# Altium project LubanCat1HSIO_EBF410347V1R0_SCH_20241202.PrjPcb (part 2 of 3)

## Sheet 07 USB3.SchDoc
size 420 x 297 mm
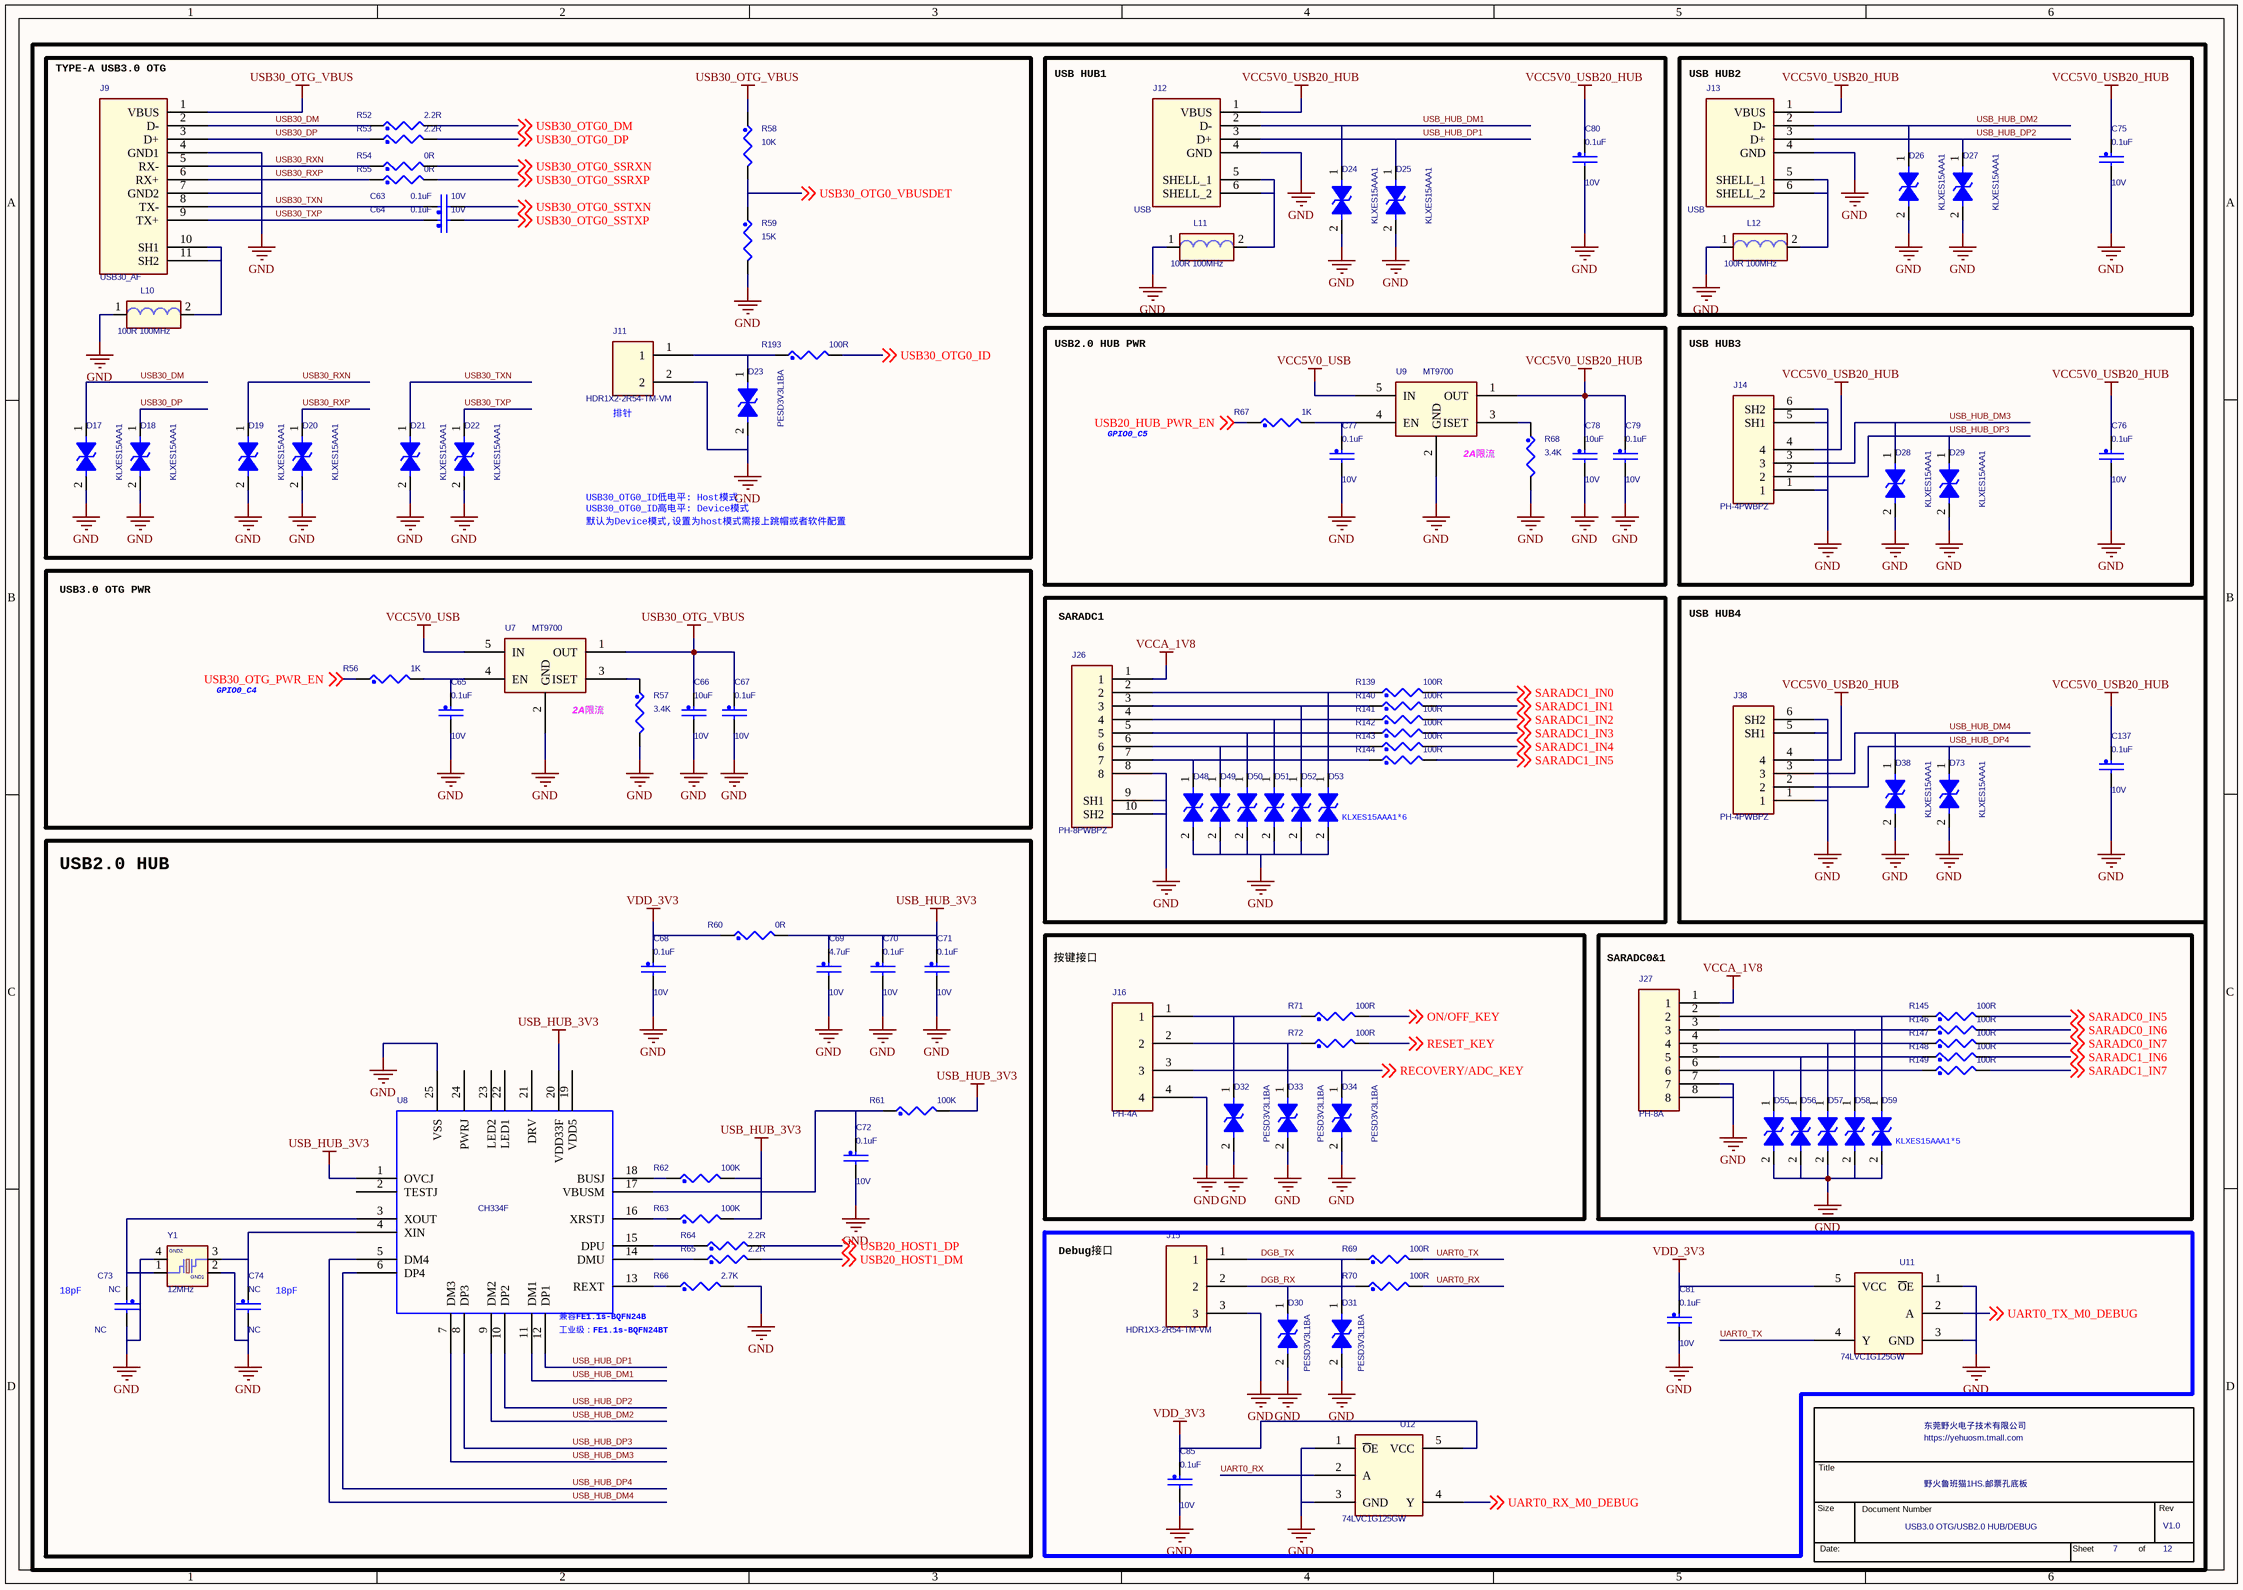
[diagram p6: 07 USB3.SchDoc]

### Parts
(Parts that share a designator on the sheet are numbered #1, #2 ... from top to bottom, then left to right.)
*#7  Page Count: 12  Page Number: 7  OrgName: 东莞野火电子技术有限公司  Title: 野火鲁班猫1HS.邮票孔底板  RevCode: V1.0  Doc: USB3.0 OTG/USB2.0 HUB/DEBUG  (hidden comment: TitleBlock_YHSCH)  (graphical)
C63  0.1uF  Voltage: 10V  [C0402]
C64  0.1uF  Voltage: 10V  [C0402]
C65  0.1uF  Voltage: 10V  [C0402]
C66  10uF  Voltage: 10V  [C0402]
C67  0.1uF  Voltage: 10V  [C0402]
C68  0.1uF  Voltage: 10V  [C0402]
C69  4.7uF  Voltage: 10V  [C0402]
C70  0.1uF  Voltage: 10V  [C0402]
C71  0.1uF  Voltage: 10V  [C0402]
C72  0.1uF  Voltage: 10V  [C0402]
C73  NC  [C0402]
C74  NC  [C0402]
C75  0.1uF  Voltage: 10V  [C0402]
C76  0.1uF  Voltage: 10V  [C0402]
C77  0.1uF  Voltage: 10V  [C0402]
C78  10uF  Voltage: 10V  [C0402]
C79  0.1uF  Voltage: 10V  [C0402]
C80  0.1uF  Voltage: 10V  [C0402]
C81  0.1uF  Voltage: 10V  [C0402]
C85  0.1uF  Voltage: 10V  [C0402]
C137  0.1uF  Voltage: 10V  [C0402]
D17  KLXES15AAA1  [D0603/SMD]
D18  KLXES15AAA1  [D0603/SMD]
D19  KLXES15AAA1  [D0603/SMD]
D20  KLXES15AAA1  [D0603/SMD]
D21  KLXES15AAA1  [D0603/SMD]
D22  KLXES15AAA1  [D0603/SMD]
D23  PESD3V3L1BA  [D0603/SMD]
D24  KLXES15AAA1  [D0603/SMD]
D25  KLXES15AAA1  [D0603/SMD]
D26  KLXES15AAA1  [D0603/SMD]
D27  KLXES15AAA1  [D0603/SMD]
D28  KLXES15AAA1  [D0603/SMD]
D29  KLXES15AAA1  [D0603/SMD]
D30  PESD3V3L1BA  [D0603/SMD]
D31  PESD3V3L1BA  [D0603/SMD]
D32  PESD3V3L1BA  [D0603/SMD]
D33  PESD3V3L1BA  [D0603/SMD]
D34  PESD3V3L1BA  [D0603/SMD]
D38  KLXES15AAA1  [D0603/SMD]
D48  KLXES15AAA1  [D0603/SMD]  (value not drawn)
D49  KLXES15AAA1  [D0603/SMD]  (value not drawn)
D50  KLXES15AAA1  [D0603/SMD]  (value not drawn)
D51  KLXES15AAA1  [D0603/SMD]  (value not drawn)
D52  KLXES15AAA1  [D0603/SMD]  (value not drawn)
D53  KLXES15AAA1  [D0603/SMD]  (value not drawn)
D55  KLXES15AAA1  [D0603/SMD]  (value not drawn)
D56  KLXES15AAA1  [D0603/SMD]  (value not drawn)
D57  KLXES15AAA1  [D0603/SMD]  (value not drawn)
D58  KLXES15AAA1  [D0603/SMD]  (value not drawn)
D59  KLXES15AAA1  [D0603/SMD]  (value not drawn)
D73  KLXES15AAA1  [D0603/SMD]
J9  USB30_AF  [USB9-A-16R5X14R45-TM]
J11  HDR1X2-2R54-TM-VM  [HDR1X2-2R54-TM-VM]
J12  USB  [USB-A-SM]
J13  USB  [USB-A-SM]
J14  PH-4PWBPZ  [ph2r0-a-1x4]
J15  HDR1X3-2R54-TM-VM  [HDR1X3-2R54-TM-VM]
J16  PH-4A  [PH-1X4-2P0]
J26  PH-8PWBPZ  [PH2R0-A-1X8]
J27  PH-8A  [ph-1x8-2p0]
J38  PH-4PWBPZ  [ph2r0-a-1x4]
L10  100R 100MHz  [L0603]
L11  100R 100MHz  [L0603]
L12  100R 100MHz  [L0603]
R52  2.2R  [R0402]
R53  2.2R  [R0402]
R54  0R  [R0402]
R55  0R  [R0402]
R56  1K  [R0402]
R57  3.4K  [R0402]
R58  10K  [R0402]
R59  15K  [R0402]
R60  0R  [R0402]
R61  100K  [R0402]
R62  100K  [R0402]
R63  100K  [R0402]
R64  2.2R  [R0402]
R65  2.2R  [R0402]
R66  2.7K  [R0402]
R67  1K  [R0402]
R68  3.4K  [R0402]
R69  100R  [R0402]
R70  100R  [R0402]
R71  100R  [R0402]
R72  100R  [R0402]
R139  100R  [R0402]
R140  100R  [R0402]
R141  100R  [R0402]
R142  100R  [R0402]
R143  100R  [R0402]
R144  100R  [R0402]
R145  100R  [R0402]
R146  100R  [R0402]
R147  100R  [R0402]
R148  100R  [R0402]
R149  100R  [R0402]
R193  100R  [R0402]
U7  MT9700  [SOT23-5]
U8  CH334F  [QFN24]
U9  MT9700  [SOT23-5]
U11  74LVC1G125GW  [SOT-353]
U12  74LVC1G125GW  [SOT-353]
Y1  12MHz  [3225]

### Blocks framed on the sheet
TYPE-A USB3.0 OTG: C63 C64 D17-D23 J9 J11 L10 R52-R55 R58 R59 R193
USB HUB1: C80 D24 D25 J12 L11
USB HUB2: C75 D26 D27 J13 L12
USB2.0 HUB PWR: C77-C79 R67 R68 U9
USB HUB3: C76 D28 D29 J14
USB3.0 OTG PWR: C65-C67 R56 R57 U7
SARADC1: D48-D53 J26 R139-R144
USB HUB4: C137 D38 D73 J38
USB2.0 HUB: C68-C74 R60-R66 U8 Y1
按键接口: D32-D34 J16 R71 R72
SARADC0&1: D55-D59 J27 R145-R149
Debug接口: C81 C85 D30 D31 J15 R69 R70 U11 U12

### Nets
GND: C65.2 C66.2 C67.2 C68.2 C69.2 C70.2 C71.2 C72.2 C73.2 C74.2 C75.2 C76.2 C77.2 C78.2 C79.2 C80.2 C81.2 C85.2 C137.2 D17.2 D18.2 D19.2 D20.2 D21.2 D22.2 D23.2 D24.2 D25.2 D26.2 D27.2 D28.2 D29.2 D30.2 D31.2 D32.2 D33.2 D34.2 D38.2 D48.2 D49.2 D50.2 D51.2 D52.2 D53.2 D55.2 D56.2 D57.2 D58.2 D59.2 D73.2 J9.4(GND1) J9.7(GND2) J11.2 J12.4(GND) J13.4(GND) J14.1 J14.5(SH1) J14.6(SH2) J15.3 J16.4 J26.8 J26.9(SH1) J26.10(SH2) J27.7 J27.8 J38.1 J38.5(SH1) J38.6(SH2) L10.1 L11.1 L12.1 R57.2 R59.2 R66.2 R68.2 U7.2(GND) U8.25(VSS) U9.2(GND) U11.1(~{O}E) U11.3(GND) U12.1(~{O}E) U12.3(GND) Y1.2(GND1) Y1.4(GND2)
USB30_OTG_VBUS: C66.1 C67.1 J9.1(VBUS) R58.1 U7.1(OUT)
USB_HUB_3V3: C69.1 C70.1 C71.1 R60.2 R61.2 R62.2 R63.2 U8.1(OVCJ) U8.20(VDD33F)
VCC5V0_USB: U7.5(IN) U9.5(IN)
VCC5V0_USB20_HUB: C75.1 C76.1 C78.1 C79.1 C80.1 C137.1 J12.1(VBUS) J13.1(VBUS) J14.4 J38.4 U9.1(OUT)
VCCA_1V8: J26.1 J27.1
VDD_3V3: C68.1 C81.1 C85.1 R60.1 U11.5(VCC) U12.5(VCC)
DGB_RX: D30.1 J15.2 R70.1
DGB_TX: D31.1 J15.1 R69.1
ON/OFF_KEY: R71.2 ; off-sheet ON/OFF_KEY
RECOVERY/ADC_KEY: D34.1 J16.3 ; off-sheet RECOVERY/ADC_KEY
RESET_KEY: R72.2 ; off-sheet RESET_KEY
SARADC0_IN5: R145.2 ; off-sheet SARADC0_IN5
SARADC0_IN6: R146.2 ; off-sheet SARADC0_IN6
SARADC0_IN7: R147.2 ; off-sheet SARADC0_IN7
SARADC1_IN0: R139.2 ; off-sheet SARADC1_IN0
SARADC1_IN1: R140.2 ; off-sheet SARADC1_IN1
SARADC1_IN2: R141.2 ; off-sheet SARADC1_IN2
SARADC1_IN3: R142.2 ; off-sheet SARADC1_IN3
SARADC1_IN4: R143.2 ; off-sheet SARADC1_IN4
SARADC1_IN5: R144.2 ; off-sheet SARADC1_IN5
SARADC1_IN6: R148.2 ; off-sheet SARADC1_IN6
SARADC1_IN7: R149.2 ; off-sheet SARADC1_IN7
UART0_RX: R70.2 U12.2(A)
UART0_RX_M0_DEBUG: U12.4(Y) ; off-sheet UART0_RX_M0_DEBUG
UART0_TX: R69.2 U11.4(Y)
UART0_TX_M0_DEBUG: U11.2(A) ; off-sheet UART0_TX_M0_DEBUG
USB20_HOST1_DM: R65.2 ; off-sheet USB20_HOST1_DM
USB20_HOST1_DP: R64.2 ; off-sheet USB20_HOST1_DP
USB20_HUB_PWR_EN: R67.1 ; off-sheet USB20_HUB_PWR_EN
USB30_DM: D17.1 J9.2(D-) R52.1
USB30_DP: D18.1 J9.3(D+) R53.1
USB30_OTG0_DM: R52.2 ; off-sheet USB30_OTG0_DM
USB30_OTG0_DP: R53.2 ; off-sheet USB30_OTG0_DP
USB30_OTG0_ID: R193.2 ; off-sheet USB30_OTG0_ID
USB30_OTG0_SSRXN: R54.2 ; off-sheet USB30_OTG0_SSRXN
USB30_OTG0_SSRXP: R55.2 ; off-sheet USB30_OTG0_SSRXP
USB30_OTG0_SSTXN: C63.2 ; off-sheet USB30_OTG0_SSTXN
USB30_OTG0_SSTXP: C64.2 ; off-sheet USB30_OTG0_SSTXP
USB30_OTG0_VBUSDET: R58.2 R59.1 ; off-sheet USB30_OTG0_VBUSDET
USB30_OTG_PWR_EN: R56.1 ; off-sheet USB30_OTG_PWR_EN
USB30_RXN: D19.1 J9.5(RX-) R54.1
USB30_RXP: D20.1 J9.6(RX+) R55.1
USB30_TXN: C63.1 D21.1 J9.8(TX-)
USB30_TXP: C64.1 D22.1 J9.9(TX+)
USB_HUB_DM1: D24.1 J12.2(D-) U8.11(DM1)
USB_HUB_DM2: D26.1 J13.2(D-) U8.9(DM2)
USB_HUB_DM3: D28.1 J14.3 U8.7(DM3)
USB_HUB_DM4: D38.1 J38.3 U8.5(DM4)
USB_HUB_DP1: D25.1 J12.3(D+) U8.12(DP1)
USB_HUB_DP2: D27.1 J13.3(D+) U8.10(DP2)
USB_HUB_DP3: D29.1 J14.2 U8.8(DP3)
USB_HUB_DP4: D73.1 J38.2 U8.6(DP4)
NetC65_1: C65.1 R56.2 U7.4(EN)
NetC72_1: C72.1 R61.1 U8.17(VBUSM)
NetC73_1: C73.1 U8.3(XOUT) Y1.1
NetC74_1: C74.1 U8.4(XIN) Y1.3
NetC77_1: C77.1 R67.2 U9.4(EN)
NetD23_1: D23.1 J11.1 R193.1
NetD32_1: D32.1 J16.1 R71.1
NetD33_1: D33.1 J16.2 R72.1
NetD48_1: D48.1 J26.7 R144.1
NetD49_1: D49.1 J26.6 R143.1
NetD50_1: D50.1 J26.5 R142.1
NetD51_1: D51.1 J26.4 R141.1
NetD52_1: D52.1 J26.3 R140.1
NetD53_1: D53.1 J26.2 R139.1
NetD55_1: D55.1 J27.6 R149.1
NetD56_1: D56.1 J27.5 R148.1
NetD57_1: D57.1 J27.4 R147.1
NetD58_1: D58.1 J27.3 R146.1
NetD59_1: D59.1 J27.2 R145.1
NetJ9_10: J9.10(SH1) J9.11(SH2) L10.2
NetJ12_5: J12.5(SHELL_1) J12.6(SHELL_2) L11.2
NetJ13_5: J13.5(SHELL_1) J13.6(SHELL_2) L12.2
NetR57_1: R57.1 U7.3(ISET)
NetR62_1: R62.1 U8.18(BUSJ)
NetR63_1: R63.1 U8.16(XRSTJ)
NetR64_1: R64.1 U8.15(DPU)
NetR65_1: R65.1 U8.14(DMU)
NetR66_1: R66.1 U8.13(REXT)
NetR68_1: R68.1 U9.3(ISET)

Not connected (* = marked no-connect by the designer): U8 2(TESTJ) 19(VDD5) 21(DRV) 22(LED1) 23(LED2) 24(PWRJ)

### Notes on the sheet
- (near J11) 排针
- GPIO0_C5
- (near U9) 2A限流
- 默认为Device模式,设置为host模式需接上跳帽或者软件配置
- USB30_OTG0_ID低电平: Host模式
  USB30_OTG0_ID高电平: Device模式
- GPIO0_C4
- (near U7) 2A限流
- (near D53) KLXES15AAA1*6
- (near D59) KLXES15AAA1*5
- (near C73) 18pF
- (near C74) 18pF
- (near U8) 兼容FE1.1s-BQFN24B
- (near U8) 工业级：FE1.1s-BQFN24BT

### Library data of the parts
*#7 = TitleBlock_YHSCH: Cage Code: 1
C63 C64 C68 C70-C72 C76 C77 C79-C81 C85 C137 = CAP_NP: CLASS: DISCRETE; 备注: H743挑战者; 生命周期: 量产; 价格: 0.003175; 规格书: 风华电容.pdf; 类别: 贴片电容0402; 品牌: 风华; 条码: EBFCIS230603155031; 规格编号: 0402B104K100NT; 规格: 贴片电容0.1uF 10% 10V X7R 0402
C65 C67 C75 = CAP_NP: CLASS: DISCRETE; 规格: 贴片电容0.1uF 10% 10V X7R 0402; 规格编号: 0402B104K100NT; 条码: EBFCIS230603155031; 品牌: 风华; 类别: 贴片电容0402; 规格书: 风华电容.pdf; 价格: 0.003175; 生命周期: 量产; 备注: H743挑战者
C66 = CAP_NP: CLASS: DISCRETE; 规格: 贴片电容10uF 20% 10V X5R 0402; 规格编号: CL05A106MP8NUB8; 条码: EBF29060247; 品牌: 三星; 类别: 贴片电容0402; 规格书: 三星电容.pdf; 价格: 0.518415; 生命周期: 量产
C69 = CAP_NP: CLASS: DISCRETE; 规格: 贴片电容4.7uF 10% 10V X5R 0402; 规格编号: CC0402KRX5R6BB475; 条码: EBF29060248; 品牌: 国巨; 类别: 贴片电容0402; 规格书: 国巨-贴片电容.pdf; 价格: 0.059058; 生命周期: 量产
C73 = CAP_NP: CLASS: DISCRETE; 规格: 贴片电容NC 预留; 条码: EBF29060149; 类别: 贴片电容0402
C74 = CAP_NP: CLASS: DISCRETE; 类别: 贴片电容0402; 条码: EBF29060149; 规格: 贴片电容NC 预留
C78 = CAP_NP: CLASS: DISCRETE; 生命周期: 量产; 价格: 0.518415; 规格书: 三星电容.pdf; 类别: 贴片电容0402; 品牌: 三星; 条码: EBF29060247; 规格编号: CL05A106MP8NUB8; 规格: 贴片电容10uF 20% 10V X5R 0402
D17 D18 D21 D22 D24 D25 D28 D29 D48-D53 = DIODE BI-DIR TRIG: 生命周期: 量产; 价格: 0.09719; 规格书: KLXES15AAA1.pdf; 类别: 贴片ESD; 品牌: 永裕泰; 条码: EBF29140063; 规格: 用于 USB3.0、HDMI 0.5pF、5V、±15kV ESD 保护二极管
D19 D20 D26 D27 D38 D55-D59 D73 = DIODE BI-DIR TRIG: 规格: 用于 USB3.0、HDMI 0.5pF、5V、±15kV ESD 保护二极管; 条码: EBF29140063; 品牌: 永裕泰; 类别: 贴片ESD; 规格书: KLXES15AAA1.pdf; 价格: 0.09719; 生命周期: 量产
D23 D32-D34 = DIODE BI-DIR TRIG: 规格: 防静电保护ESD二极管 箝位电压26V 击穿电压5.8V 反向关断电压3.3V; 规格编号: PESD3V3L1BA 115; 条码: EBF29140003; 品牌: 安世; 类别: 贴片ESD; 规格书: 安世-PESD3V3L1BA-115.pdf; 价格: 0.31497; 生命周期: 量产; 丝印: AB
D30 D31 = DIODE BI-DIR TRIG: 丝印: AB; 生命周期: 量产; 价格: 0.31497; 规格书: 安世-PESD3V3L1BA-115.pdf; 类别: 贴片ESD; 品牌: 安世; 条码: EBF29140003; 规格编号: PESD3V3L1BA 115; 规格: 防静电保护ESD二极管 箝位电压26V 击穿电压5.8V 反向关断电压3.3V
J9 = USB30_AF: 备注: RK3566广告机; 生命周期: 量产; 规格书: 讯普_USB3.0-TYPE-A母座弯插.pdf; 类别: USB接口; 品牌: 讯普; 条码: EBFCIS230517183858; 规格编号: USB-301WD-ARY; 规格: USB3.0 Type-A 母座 AF 90°弯插 蓝胶 触点数量9
J11 = 1X2PIN: 规格: 蓝色直插单排排针 总PIN数2 间距2.54mm; 规格编号: HDR1X2-2R54-TM-VM-BLUE; 条码: EBF29020019; 品牌: 州日; 类别: 2.54mm直插单排排针; 规格书: 州日_单排针_直插_2P54.pdf; 价格: 0.02; 生命周期: 量产
J12 J13 = USB Conn.-Fem-TypeA-TH-RA: P/N: 180K00400S; 规格: Type-A 母座 AF90°弯插 白胶 卷边有后盖 铁壳 触点数量4 额定电流1.5A; 规格编号: USB-U212-BJS; 条码: EBF29040127; 品牌: 汉博; 类别: USB接口; 规格书: TYPE-A母座AF90°弯插白胶卷边有后盖铁壳.pdf; 生命周期: 量产
J14 = 1X4PIN_SH: 生命周期: 量产; 价格: 0.23158; 规格书: 博穆精密_PH2.0-A.pdf; 类别: PH连接器; 品牌: 博穆精密; 条码: EBF29040117; 规格: 间距：2mm 插针结构：1x4P 排数：1 每排PIN数：4 公母：公型插针 安装方式：卧贴 额定电流：2A 工作温度范围：-25℃~+85℃
J15 = 1X3PIN: 价格: 0.06; 品牌: 州日; 规格编号: HDR1X3-2R54-TM-VM-BLUE; 生命周期: 量产; 类别: 2.54mm直插单排排针; 条码: EBF29020046; 规格: 蓝色直插单排排针 总PIN数3 间距2.54mm; 规格书: 州日_单排针_直插_2P54.pdf
J16 = 1X4PIN: 可替代料: EBF29020025; 生命周期: 量产; 价格: 0.017; 规格书: 博穆精密-PH2.0.pdf; 类别: PH连接器; 品牌: 博穆精密; 规格: 直针PH2.0-4P 间距2.0MM 拔插式 接插件
J26 = 1X8PIN_SH: 备注: RK3562邮票孔底板; 生命周期: 量产; 价格: 0.648177; 规格书: 博穆精密_PH2.0-A.pdf; 类别: PH连接器; 品牌: 博穆精密; 条码: EBFCIS230829011841; 规格: 间距：2mm 插针结构：1x8P 排数：1 每排PIN数：8 公母：公型插针 安装方式：卧贴 额定电流：2A 工作温度范围：-25℃~+85℃
J27 = 1X8PIN: 备注: RK3562邮票孔底板; 生命周期: 量产; 价格: 0.206072; 规格书: 博穆精密-PH2.0.pdf; 类别: PH连接器; 品牌: 博穆精密; 条码: EBFCIS230829011232; 规格: 直针PH2.0-8P 间距2.0MM 拔插式 接插件
J38 = 1X4PIN_SH: 规格: 间距：2mm 插针结构：1x4P 排数：1 每排PIN数：4 公母：公型插针 安装方式：卧贴 额定电流：2A 工作温度范围：-25℃~+85℃; 条码: EBF29040117; 品牌: 博穆精密; 类别: PH连接器; 规格书: 博穆精密_PH2.0-A.pdf; 价格: 0.23158; 生命周期: 量产
L10 = BEAD: CLASS: DISCRETE; 生命周期: 量产; 价格: 0.021567; 规格书: 顺络-磁珠.pdf; 类别: 贴片磁珠0603; 品牌: 顺络; 条码: EBF29050038; 规格编号: UPZ1608E101-3R0TF; 规格: 磁珠100Ω @100MHz 额定电流3A 直流电阻30mΩ
L11 L12 = BEAD: CLASS: DISCRETE; 规格: 磁珠100Ω @100MHz 额定电流3A 直流电阻30mΩ; 规格编号: UPZ1608E101-3R0TF; 条码: EBF29050038; 品牌: 顺络; 类别: 贴片磁珠0603; 规格书: 顺络-磁珠.pdf; 价格: 0.021567; 生命周期: 量产
R52 R53 R64 R65 = RES: CLASS: DISCRETE; 生命周期: 量产; 价格: 0.003072; 规格书: 厚声-无铅厚膜电阻.pdf; 类别: 贴片电阻0402; 品牌: 厚声; 条码: EBF29070280; 规格编号: 0402WGF220KTCE; 规格: 贴片电阻2.2R 1% 1/16W 0402
R54 R55 R60 = RES: CLASS: DISCRETE; 生命周期: 量产; 规格书: 合科泰-RI系列电阻.pdf; 类别: 贴片电阻0402; 品牌: 合科泰; 条码: EBF29070049; 规格编号: RI0402L000FT; 规格: 贴片电阻0R 1% 1/16W 0402
R56 = RES: CLASS: DISCRETE; 生命周期: 量产; 规格书: 合科泰-RI系列电阻.pdf; 类别: 贴片电阻0402; 品牌: 合科泰; 条码: EBF29070050; 规格编号: RI0402L1001FT; 规格: 贴片电阻1K 1% 1/16W 0402
R57 = RES: CLASS: DISCRETE; 生命周期: 量产; 规格书: 合科泰-RI系列电阻.pdf; 类别: 贴片电阻0402; 品牌: 合科泰; 条码: EBF29070186; 规格编号: RI0402L3401FT; 规格: 贴片电阻3.4K 1% 1/16W 0402
R58 = RES: CLASS: DISCRETE; 生命周期: 量产; 价格: 0.002773; 规格书: 厚声-无铅厚膜电阻.pdf; 类别: 贴片电阻0402; 品牌: 厚声; 条码: EBF29070046; 规格编号: 0402WGF1002TCE; 规格: 贴片电阻10K 1% 1/16W 0402
R59 = RES: CLASS: DISCRETE; 规格: 贴片电阻15K 1% 1/16W 0402; 规格编号: RI0402L1502FT; 条码: EBF29070222; 品牌: 合科泰; 类别: 贴片电阻0402; 规格书: 合科泰-RI系列电阻.pdf; 生命周期: 量产
R61-R63 = RES: CLASS: DISCRETE; 规格: 贴片电阻100K 1% 1/16W 0402; 规格编号: RI0402L1003FT; 条码: EBF29070054; 品牌: 合科泰; 类别: 贴片电阻0402; 规格书: 合科泰-RI系列电阻.pdf; 生命周期: 量产
R66 = RES: CLASS: DISCRETE; 规格: 贴片电阻2.7K 1% 1/16W 0402; 规格编号: RMC04022.7K1%N; 条码: EBF29070202; 品牌: 幸亚; 类别: 贴片电阻0402; 规格书: 幸亚电阻.pdf; 价格: 0.016497; 生命周期: 量产
R67 = RES: CLASS: DISCRETE; 规格: 贴片电阻1K 1% 1/16W 0402; 规格编号: RI0402L1001FT; 条码: EBF29070050; 品牌: 合科泰; 类别: 贴片电阻0402; 规格书: 合科泰-RI系列电阻.pdf; 生命周期: 量产
R68 = RES: CLASS: DISCRETE; 规格: 贴片电阻3.4K 1% 1/16W 0402; 规格编号: RI0402L3401FT; 条码: EBF29070186; 品牌: 合科泰; 类别: 贴片电阻0402; 规格书: 合科泰-RI系列电阻.pdf; 生命周期: 量产
R69-R72 R139-R144 R193 = RES: CLASS: DISCRETE; 规格: 贴片电阻100R 1% 1/16W 0402; 规格编号: RI0402L1000FT; 条码: EBF29070053; 品牌: 合科泰; 类别: 贴片电阻0402; 规格书: 合科泰-RI系列电阻.pdf; 生命周期: 量产
R145-R149 = RES: CLASS: DISCRETE; 生命周期: 量产; 规格书: 合科泰-RI系列电阻.pdf; 类别: 贴片电阻0402; 品牌: 合科泰; 条码: EBF29070053; 规格编号: RI0402L1000FT; 规格: 贴片电阻100R 1% 1/16W 0402
U7 = MT9700: 规格: 负载开关 工作电压2.4V-5.5V 最大电流2A 过流保护; 条码: EBF29280004; 品牌: 西安航天民芯; 类别: 功率开关; 规格书: MT9700.pdf; 价格: 0.483492; 生命周期: 量产; 丝印: D00HA-X
U8 = FE1.1s-BQFN24B: 生命周期: 量产; 规格书: 南京沁恒_CH334F.pdf; 类别: USB芯片; 品牌: 南京沁恒; 条码: EBFCIS221222095807; 规格: USB HUB芯片 工作电压3.3V 5V 协议类别USB2.0 支持高速(480Mbps) 全速(12Mbps)和低速(1.5Mbps)模式
U9 = MT9700: 丝印: D00HA-X; 生命周期: 量产; 价格: 0.483492; 规格书: MT9700.pdf; 类别: 功率开关; 品牌: 西安航天民芯; 条码: EBF29280004; 规格: 负载开关 工作电压2.4V-5.5V 最大电流2A 过流保护
U11 U12 = 74LVC1G125: 规格: 时钟缓冲器 驱动器 具有三态输出 允许工作电压为3.3V 5.5V 典型工作电流100mA; 条码: EBF29170001; 品牌: 安世; 类别: 隔离器件; 规格书: 74LVC1G125GW.pdf; 价格: 0.182409; 生命周期: 量产; 丝印: VM
Y1 = CRYSTAL_4P: CLASS: IC; 规格: 无源晶振12MHZ 80Ω 20pF 3225; 规格编号: X322512MSB4SI; 条码: EBF29100013; 品牌: 扬兴科技; 类别: 贴片晶振 3225; 规格书: 扬兴科技-贴片晶振.pdf; 价格: 0.327763; 生命周期: 量产

## Sheet 08 LED_IR_GPIO引出_MASKRO.SchDoc
size 297 x 209 mm
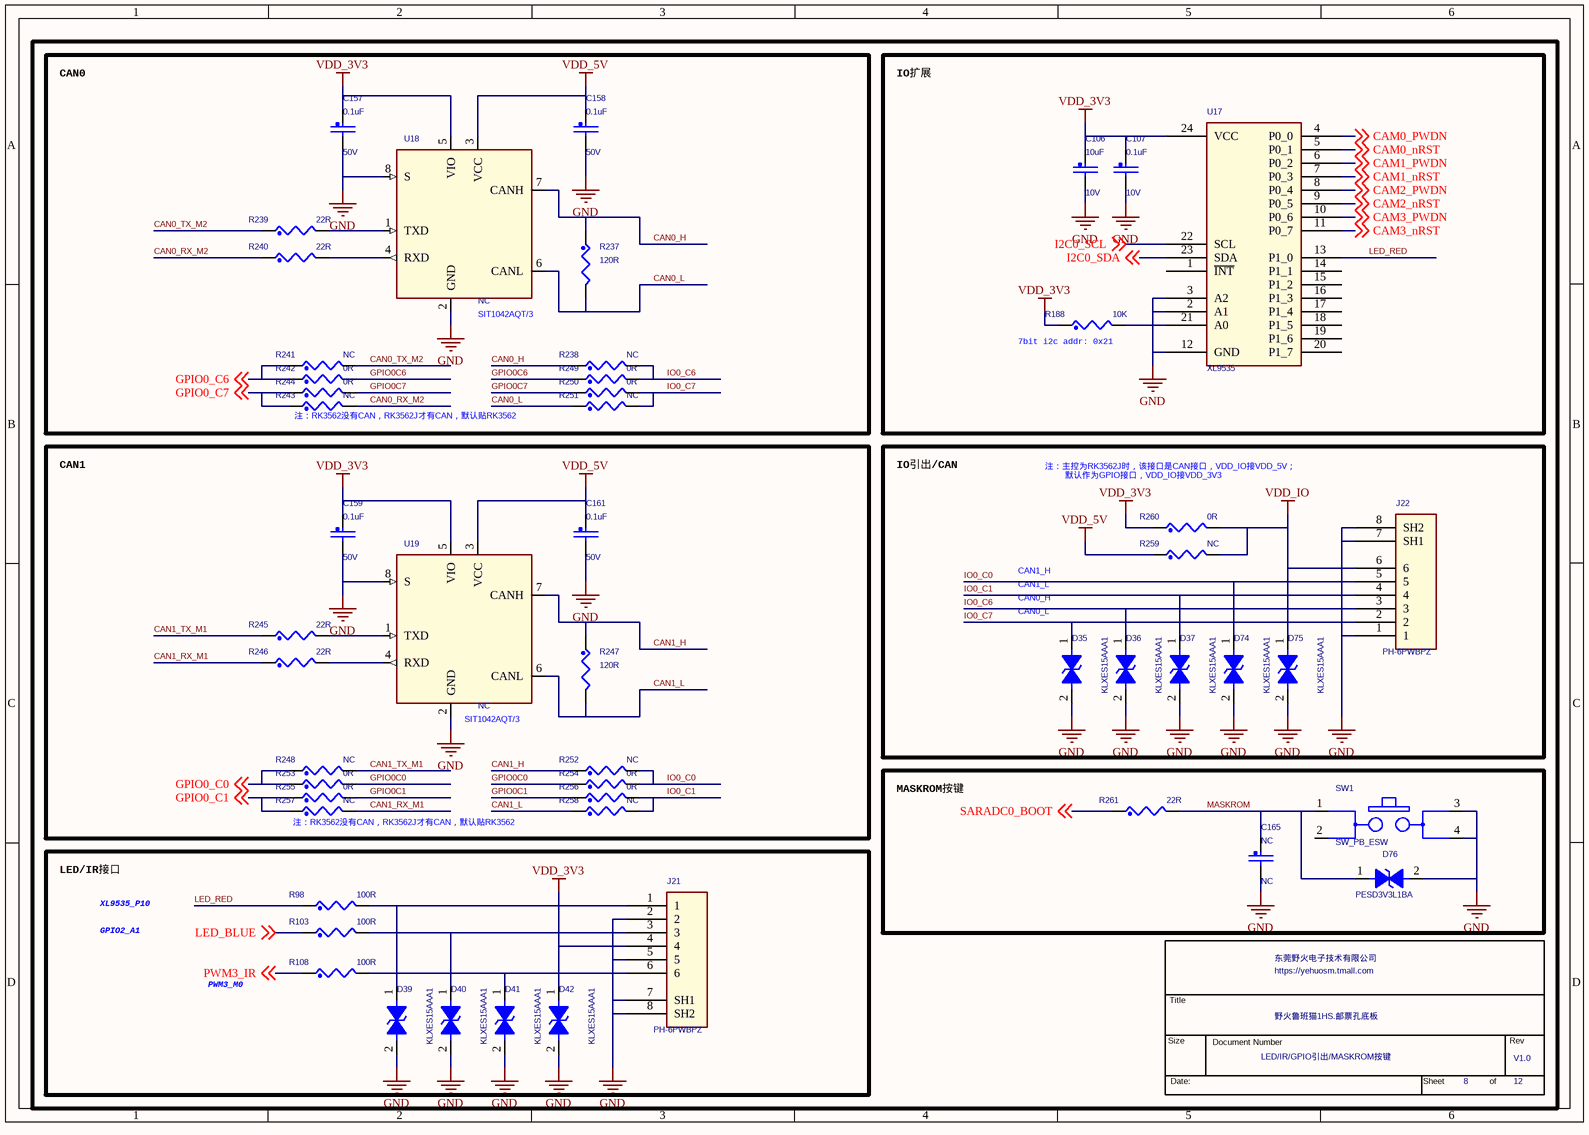
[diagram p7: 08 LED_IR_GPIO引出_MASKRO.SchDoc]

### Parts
(Parts that share a designator on the sheet are numbered #1, #2 ... from top to bottom, then left to right.)
*#8  Page Count: 12  Page Number: 8  OrgName: 东莞野火电子技术有限公司  Title: 野火鲁班猫1HS.邮票孔底板  RevCode: V1.0  Doc: LED/IR/GPIO引出/MASKROM按键  (hidden comment: TitleBlock_YHSCH)  (graphical)
C106  10uF  Voltage: 10V  [C0402]
C107  0.1uF  Voltage: 10V  [C0402]
C157  0.1uF  Voltage: 50V  [C0402]
C158  0.1uF  Voltage: 50V  [C0402]
C159  0.1uF  Voltage: 50V  [C0402]
C161  0.1uF  Voltage: 50V  [C0402]
C165  NC  [C0402]
D35  KLXES15AAA1  [D0603/SMD]
D36  KLXES15AAA1  [D0603/SMD]
D37  KLXES15AAA1  [D0603/SMD]
D39  KLXES15AAA1  [D0603/SMD]
D40  KLXES15AAA1  [D0603/SMD]
D41  KLXES15AAA1  [D0603/SMD]
D42  KLXES15AAA1  [D0603/SMD]
D74  KLXES15AAA1  [D0603/SMD]
D75  KLXES15AAA1  [D0603/SMD]
D76  PESD3V3L1BA  [D0603/SMD]
J21  PH-6PWBPZ  [PH2R0-A-1X6]
J22  PH-6PWBPZ  [PH2R0-A-1X6]
R98  100R  [R0402]
R103  100R  [R0402]
R108  100R  [R0402]
R188  10K  [R0402]
R237  120R  [R0402]
R238  NC  [R0402]
R239  22R  [R0402]
R240  22R  [R0402]
R241  NC  [R0402]
R242  0R  [R0402]
R243  NC  [R0402]
R244  0R  [R0402]
R245  22R  [R0402]
R246  22R  [R0402]
R247  120R  [R0402]
R248  NC  [R0402]
R249  0R  [R0402]
R250  0R  [R0402]
R251  NC  [R0402]
R252  NC  [R0402]
R253  0R  [R0402]
R254  0R  [R0402]
R255  0R  [R0402]
R256  0R  [R0402]
R257  NC  [R0402]
R258  NC  [R0402]
R259  NC  [R0402]
R260  0R  [R0402]
R261  22R  [R0402]
SW1  SW_PB_ESW  [SW4-4R20X3R25-SM]
U17  XL9535  [TSSOP24-0R65-7R80X4R40]
U18  NC  [SOP8]
U19  NC  [SOP8]

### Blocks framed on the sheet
CAN0: C157 C158 R237-R244 R249-R251 U18
IO扩展: C106 C107 R188 U17
CAN1: C159 C161 R245-R248 R252-R258 U19
IO引出/CAN: D35-D37 D74 D75 J22 R259 R260
MASKROM按键: C165 D76 R261 SW1
LED/IR接口: D39-D42 J21 R98 R103 R108

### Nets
GND: C106.2 C107.2 C157.2 C158.2 C159.2 C161.2 C165.2 D35.2 D36.2 D37.2 D39.2 D40.2 D41.2 D42.2 D74.2 D75.2 D76.2 J21.2 J21.5 J21.7(SH1) J21.8(SH2) J22.1 J22.7(SH1) J22.8(SH2) SW1.3(B1) SW1.4(B2) U17.2(A1) U17.3(A2) U17.12(GND) U18.2(GND) U18.8(S) U19.2(GND) U19.8(S)
VDD_3V3: C106.1 C107.1 C157.1 C159.1 D42.1 J21.4 R188.1 R260.1 U17.24(VCC) U18.5(VIO) U19.5(VIO)
VDD_5V: C158.1 C161.1 R259.1 U18.3(VCC) U19.3(VCC)
VDD_IO: D75.1 J22.6 R259.2 R260.2
CAM0_nRST: U17.5(P0_1) ; off-sheet CAM0_nRST
CAM0_PWDN: U17.4(P0_0) ; off-sheet CAM0_PWDN
CAM1_nRST: U17.7(P0_3) ; off-sheet CAM1_nRST
CAM1_PWDN: U17.6(P0_2) ; off-sheet CAM1_PWDN
CAM2_nRST: U17.9(P0_5) ; off-sheet CAM2_nRST
CAM2_PWDN: U17.8(P0_4) ; off-sheet CAM2_PWDN
CAM3_nRST: U17.11(P0_7) ; off-sheet CAM3_nRST
CAM3_PWDN: U17.10(P0_6) ; off-sheet CAM3_PWDN
CAN0_H: R237.1 R238.1 U18.7(CANH)
CAN0_L: R237.2 R251.1 U18.6(CANL)
CAN0_RX_M2: R240.1 R243.2
CAN0_TX_M2: R239.1 R241.2
CAN1_H: R247.1 R252.1 U19.7(CANH)
CAN1_L: R247.2 R258.1 U19.6(CANL)
CAN1_RX_M1: R246.1 R257.2
CAN1_TX_M1: R245.1 R248.2
GPIO0_C0: R248.1 R253.1 ; off-sheet GPIO0_C0
GPIO0_C1: R255.1 R257.1 ; off-sheet GPIO0_C1
GPIO0_C6: R241.1 R242.1 ; off-sheet GPIO0_C6
GPIO0_C7: R243.1 R244.1 ; off-sheet GPIO0_C7
GPIO0C0: R253.2 R254.1
GPIO0C1: R255.2 R256.1
GPIO0C6: R242.2 R249.1
GPIO0C7: R244.2 R250.1
I2C0_SCL: U17.22(SCL) ; off-sheet I2C0_SCL
I2C0_SDA: U17.23(SDA) ; off-sheet I2C0_SDA
IO0_C0: D74.1 J22.5 R252.2 R254.2
IO0_C1: D37.1 J22.4 R256.2 R258.2
IO0_C6: D36.1 J22.3 R238.2 R249.2
IO0_C7: D35.1 J22.2 R250.2 R251.2
LED_BLUE: R103.1 ; off-sheet LED_BLUE
LED_RED: R98.1 U17.13(P1_0)
MASKROM: C165.1 D76.1 R261.2 SW1.1(A1)
PWM3_IR: R108.1 ; off-sheet PWM3_IR
SARADC0_BOOT: R261.1 ; off-sheet SARADC0_BOOT
NetD39_1: D39.1 J21.1 R98.2
NetD40_1: D40.1 J21.3 R103.2
NetD41_1: D41.1 J21.6 R108.2
NetR188_2: R188.2 U17.21(A0)
NetR239_2: R239.2 U18.1(TXD)
NetR240_2: R240.2 U18.4(RXD)
NetR245_2: R245.2 U19.1(TXD)
NetR246_2: R246.2 U19.4(RXD)

Not connected (* = marked no-connect by the designer): SW1 2(A2); U17 1(~{INT}) 14(P1_1) 15(P1_2) 16(P1_3) 17(P1_4) 18(P1_5) 19(P1_6) 20(P1_7)

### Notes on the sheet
- (near U18) SIT1042AQT/3
- (near R188) 7bit i2c addr: 0x21
- (near R243) 注：RK3562没有CAN，RK3562J才有CAN，默认贴RK3562
- 注：主控为RK3562J时，该接口是CAN接口，VDD_IO接VDD_5V；
  默认作为GPIO接口，VDD_IO接VDD_3V3
- (near D35) CAN0_H
- CAN1_H
- CAN1_L
- (near D35) CAN0_L
- (near U19) SIT1042AQT/3
- (near R257) 注：RK3562没有CAN，RK3562J才有CAN，默认贴RK3562
- GPIO2_A1
- XL9535_P10
- PWM3_M0

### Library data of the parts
*#8 = TitleBlock_YHSCH: Cage Code: 1
C106 = CAP_NP: as C78 on sheet 07 USB3
C107 = CAP_NP: as C65 on sheet 07 USB3
C157-C159 C161 = CAP_NP: CLASS: DISCRETE; 规格: 贴片电容0.1uF 10% 50V X5R 0402; 规格编号: 0402X104K500NT; 条码: EBF29060118; 品牌: 风华; 类别: 贴片电容0402; 规格书: 风华电容.pdf; 价格: 0.029826; 生命周期: 量产
C165 = CAP_NP: as C73 on sheet 07 USB3
D35-D37 D39-D42 D74 D75 = DIODE BI-DIR TRIG: as D19 on sheet 07 USB3
D76 = DIODE BI-DIR TRIG: as D30 on sheet 07 USB3
J21 J22 = 1X6PIN_SH: 生命周期: 量产; 价格: 0.47; 规格书: 博穆精密_PH2.0-A.pdf; 类别: PH连接器; 品牌: 博穆精密; 条码: EBFCIS230215171117; 规格: 间距：2mm 插针结构：1x6P 排数：1 每排PIN数：6 公母：公型插针 安装方式：卧贴 额定电流：2A 工作温度范围：-25℃~+85℃
R98 R103 = RES: as R145-R149 on sheet 07 USB3
R108 = RES: as R69 on sheet 07 USB3
R188 = RES: CLASS: DISCRETE; 规格: 贴片电阻10K 1% 1/16W 0402; 规格编号: 0402WGF1002TCE; 条码: EBF29070046; 品牌: 厚声; 类别: 贴片电阻0402; 规格书: 厚声-无铅厚膜电阻.pdf; 价格: 0.002773; 生命周期: 量产
R237 R247 = RES: CLASS: DISCRETE; 价格: 0.002198; 规格: 贴片电阻120R 1% 1/16W 0402; 规格编号: 0402WGF1200TCE; 条码: EBF29070275; 品牌: 厚声; 类别: 贴片电阻0402; 规格书: 厚声-无铅厚膜电阻.pdf; 生命周期: 量产
R238 R241 R243 R248 R251 R252 R257 R258 = RES: CLASS: DISCRETE; 规格: 贴片电阻NC 预留; 条码: EBF29070087; 类别: 贴片电阻0402
R239 R240 R245 R246 = RES: CLASS: DISCRETE; 规格: 贴片电阻22R 1% 1/16W 0402; 规格编号: RI0402L22R0FT; 条码: EBF29070181; 品牌: 合科泰; 类别: 贴片电阻0402; 规格书: 合科泰-RI系列电阻.pdf; 生命周期: 量产
R242 R249 R253 R254 = RES: as R54 on sheet 07 USB3
R244 R250 R255 R256 R260 = RES: CLASS: DISCRETE; 规格: 贴片电阻0R 1% 1/16W 0402; 规格编号: RI0402L000FT; 条码: EBF29070049; 品牌: 合科泰; 类别: 贴片电阻0402; 规格书: 合科泰-RI系列电阻.pdf; 生命周期: 量产
R259 = RES: CLASS: DISCRETE; 类别: 贴片电阻0402; 条码: EBF29070087; 规格: 贴片电阻NC 预留
R261 = RES: CLASS: DISCRETE; 生命周期: 量产; 规格书: 合科泰-RI系列电阻.pdf; 类别: 贴片电阻0402; 品牌: 合科泰; 条码: EBF29070181; 规格编号: RI0402L22R0FT; 规格: 贴片电阻22R 1% 1/16W 0402
SW1 = SW_PB_ESW: CLASS: IC; 规格: 3×4×2.5 160gf 轻触开关 白色; 规格编号: TS-1089U-AR02526; 条码: EBF29310006; 品牌: 讯普; 类别: 贴片轻触开关; 规格书: 讯普3×4×2.5160GF轻触开.pdf; 价格: 0.168282; 生命周期: 量产; 备注: 修正封装
U17 = XL9535: 丝印: XL9535D; 备注: RK3588 BTB底板; 生命周期: 量产; 价格: 1.75; 规格书: 信路达_XL9535.pdf; 类别: IO拓展; 品牌: 信路达; 条码: EBFCIS230803102100; 规格: I2C接口 16个双向输入输出引脚 支持中断输出 工作电压2.3V~5.5V
U18 U19 = TJA1057GT3_8P: CLASS: IC; 类别: CAN芯片

## Sheet 09 MIPI DSI_LVDS接口.SchDoc
size 420 x 297 mm
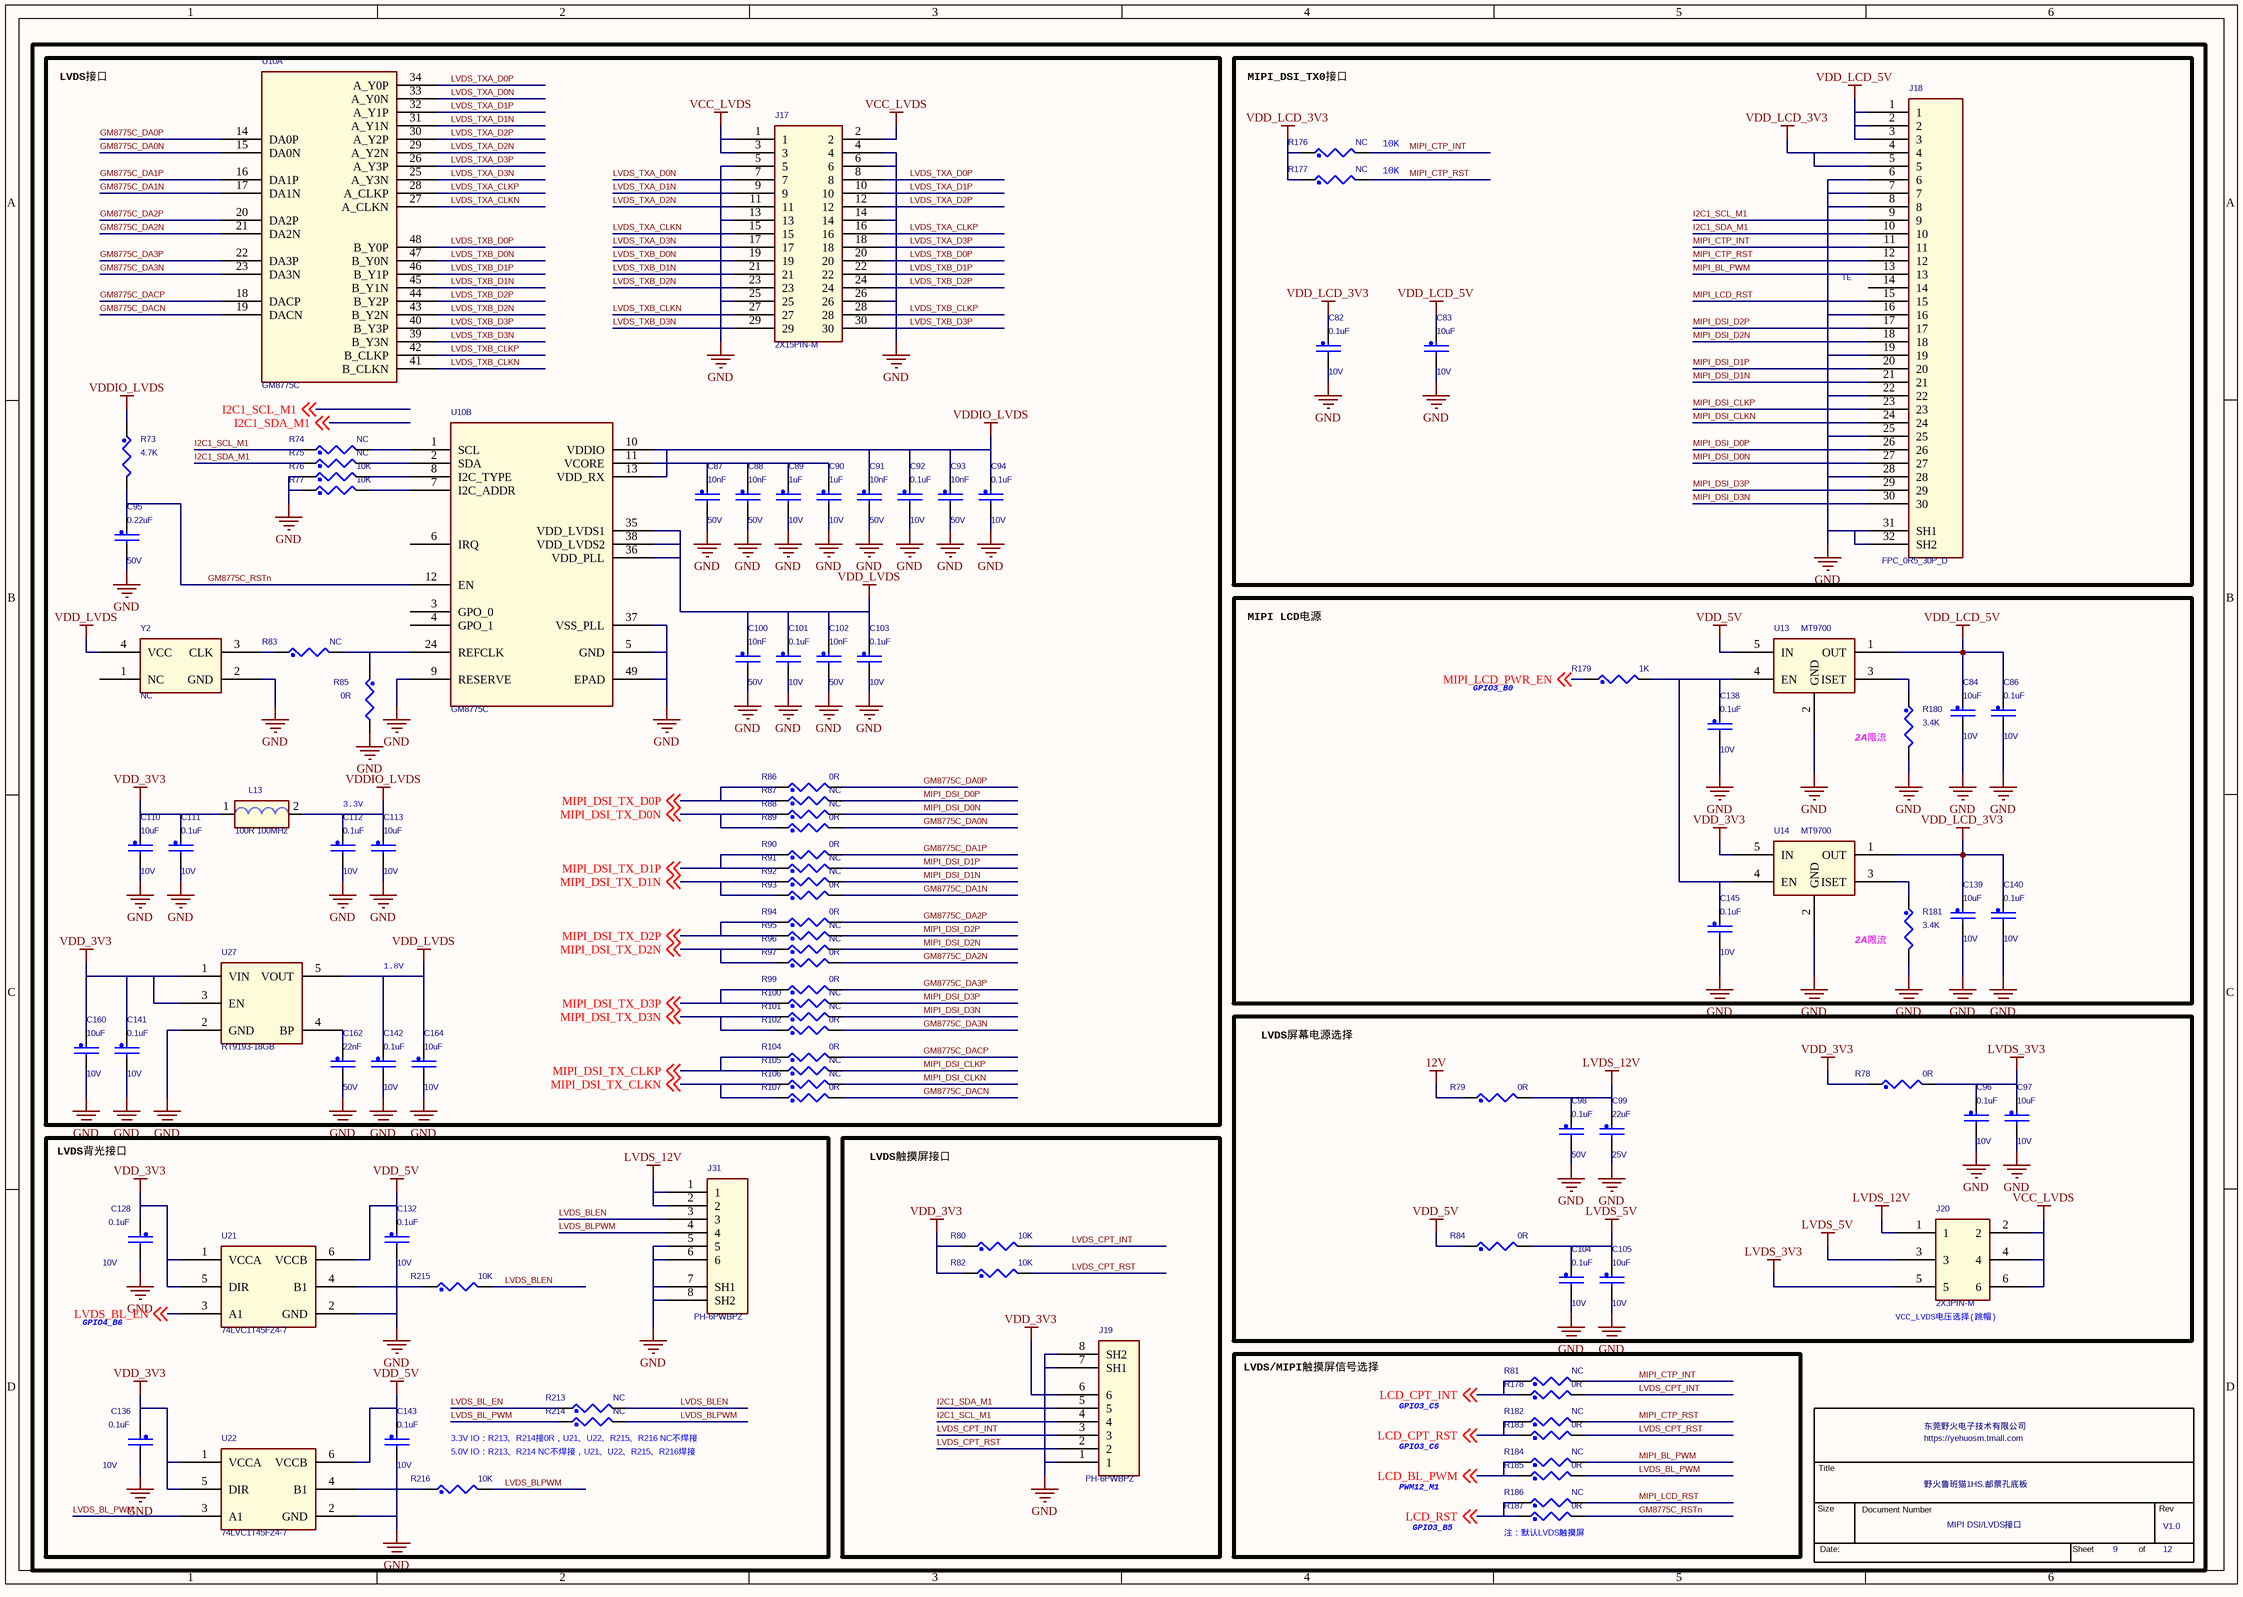
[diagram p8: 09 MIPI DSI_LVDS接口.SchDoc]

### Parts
(Parts that share a designator on the sheet are numbered #1, #2 ... from top to bottom, then left to right.)
*#9  Page Count: 12  Page Number: 9  OrgName: 东莞野火电子技术有限公司  Title: 野火鲁班猫1HS.邮票孔底板  RevCode: V1.0  Doc: MIPI DSI/LVDS接口  (hidden comment: TitleBlock_YHSCH)  (graphical)
C82  0.1uF  Voltage: 10V  [C0402]
C83  10uF  Voltage: 10V  [C0402]
C84  10uF  Voltage: 10V  [C0402]
C86  0.1uF  Voltage: 10V  [C0402]
C87  10nF  Voltage: 50V  [C0402]
C88  10nF  Voltage: 50V  [C0402]
C89  1uF  Voltage: 10V  [C0402]
C90  1uF  Voltage: 10V  [C0402]
C91  10nF  Voltage: 50V  [C0402]
C92  0.1uF  Voltage: 10V  [C0402]
C93  10nF  Voltage: 50V  [C0402]
C94  0.1uF  Voltage: 10V  [C0402]
C95  0.22uF  Voltage: 50V  [C0402]
C96  0.1uF  Voltage: 10V  [C0402]
C97  10uF  Voltage: 10V  [C0402]
C98  0.1uF  Voltage: 50V  [C0402]
C99  22uF  Voltage: 25V  [C0805]
C100  10nF  Voltage: 50V  [C0402]
C101  0.1uF  Voltage: 10V  [C0402]
C102  10nF  Voltage: 50V  [C0402]
C103  0.1uF  Voltage: 10V  [C0402]
C104  0.1uF  Voltage: 10V  [C0402]
C105  10uF  Voltage: 10V  [C0402]
C110  10uF  Voltage: 10V  [C0402]
C111  0.1uF  Voltage: 10V  [C0402]
C112  0.1uF  Voltage: 10V  [C0402]
C113  10uF  Voltage: 10V  [C0402]
C128  0.1uF  Voltage: 10V  [C0402]
C132  0.1uF  Voltage: 10V  [C0402]
C136  0.1uF  Voltage: 10V  [C0402]
C138  0.1uF  Voltage: 10V  [C0402]
C139  10uF  Voltage: 10V  [C0402]
C140  0.1uF  Voltage: 10V  [C0402]
C141  0.1uF  Voltage: 10V  [C0402]
C142  0.1uF  Voltage: 10V  [C0402]
C143  0.1uF  Voltage: 10V  [C0402]
C145  0.1uF  Voltage: 10V  [C0402]
C160  10uF  Voltage: 10V  [C0402]
C162  22nF  Voltage: 50V  [C0402]
C164  10uF  Voltage: 10V  [C0402]
J17  2X15PIN-M  [HDR1X15-2-TM-RM]
J18  FPC_0R5_30P_D  [FPC-30P-0P5]
J19  PH-6PWBPZ  [PH2R0-A-1X6]
J20  2X3PIN-M  [HDR2X3-2R00-TM-VM]
J31  PH-6PWBPZ  [PH2R0-A-1X6]
L13  100R 100MHz  [L0603]
R73  4.7K  [R0402]
R74  NC  [R0402]
R75  NC  [R0402]
R76  10K  [R0402]
R77  10K  [R0402]
R78  0R  [R0603]
R79  0R  [R0603]
R80  10K  [R0402]
R81  NC  [R0402]
R82  10K  [R0402]
R83  NC  [R0402]
R84  0R  [R0603]
R85  0R  [R0402]
R86  0R  [R0201]
R87  NC  [R0201]
R88  NC  [R0201]
R89  0R  [R0201]
R90  0R  [R0201]
R91  NC  [R0201]
R92  NC  [R0201]
R93  0R  [R0201]
R94  0R  [R0201]
R95  NC  [R0201]
R96  NC  [R0201]
R97  0R  [R0201]
R99  0R  [R0201]
R100  NC  [R0201]
R101  NC  [R0201]
R102  0R  [R0201]
R104  0R  [R0201]
R105  NC  [R0201]
R106  NC  [R0201]
R107  0R  [R0201]
R176  NC  [R0402]
R177  NC  [R0402]
R178  0R  [R0402]
R179  1K  [R0402]
R180  3.4K  [R0402]
R181  3.4K  [R0402]
R182  NC  [R0402]
R183  0R  [R0402]
R184  NC  [R0402]
R185  0R  [R0402]
R186  NC  [R0402]
R187  0R  [R0402]
R213  NC  [R0402]
R214  NC  [R0402]
R215  10K  [R0402]
R216  10K  [R0402]
U10  GM8775C  [QFN45-0R50-7R10X7R10EP5R40X5R40]  (parts A,B of 2)
U13  MT9700  [SOT23-5]
U14  MT9700  [SOT23-5]
U21  74LVC1T45FZ4-7  [SC70]
U22  74LVC1T45FZ4-7  [SC70]
U27  RT9193-18GB  [SOT23-5]
Y2  NC  [3225]

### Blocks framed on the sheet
LVDS接口: C87-C95 C100-C103 C110-C113 C141 C142 C160 C162 C164 J17 L13 R73-R77 R83 R85-R97 R99-R102 R104-R107 U10 U27 Y2
MIPI_DSI_TX0接口: C82 C83 J18 R176 R177
MIPI LCD电源: C84 C86 C138-C140 C145 R179-R181 U13 U14
LVDS屏幕电源选择: C96-C99 C104 C105 J20 R78 R79 R84
LVDS背光接口: C128 C132 C136 C143 J31 R213-R216 U21 U22
LVDS触摸屏接口: J19 R80 R82
LVDS/MIPI触摸屏信号选择: R81 R178 R182-R187

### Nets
12V: R79.1
GND: C82.2 C83.2 C84.2 C86.2 C87.2 C88.2 C89.2 C90.2 C91.2 C92.2 C93.2 C94.2 C95.2 C96.2 C97.2 C98.2 C99.2 C100.2 C101.2 C102.2 C103.2 C104.2 C105.2 C110.2 C111.2 C112.2 C113.2 C128.2 C132.2 C136.2 C138.2 C139.2 C140.2 C141.2 C142.2 C143.2 C145.2 C160.2 C162.2 C164.2 J17.4 J17.5 J17.6 J17.13 J17.14 J17.25 J17.26 J18.6 J18.7 J18.8 J18.16 J18.19 J18.22 J18.25 J18.28 J18.31(SH1) J18.32(SH2) J19.1 J19.7(SH1) J19.8(SH2) J31.5 J31.6 J31.7(SH1) J31.8(SH2) R76.1 R77.1 R85.2 R180.2 R181.2 U10.5(GND) U10.9(RESERVE) U10.37(VSS_PLL) U10.49(EPAD) U13.2(GND) U14.2(GND) U21.2(GND) U22.2(GND) U27.2(GND) Y2.2(GND)
LVDS_3V3: C96.1 C97.1 J20.5 R78.2
LVDS_5V: C104.1 C105.1 J20.3 R84.2
LVDS_12V: C98.1 C99.1 J20.1 J31.1 J31.2 R79.2
VCC_LVDS: J17.1 J17.2 J17.3 J20.2 J20.4 J20.6
VDD_3V3: C110.1 C111.1 C128.1 C136.1 C141.1 C160.1 J19.6 L13.1 R78.1 R80.1 R82.1 U14.5(IN) U21.1(VCCA) U21.5(DIR) U22.1(VCCA) U22.5(DIR) U27.1(VIN) U27.3(EN)
VDD_5V: C132.1 C143.1 R84.1 U13.5(IN) U21.6(VCCB) U22.6(VCCB)
VDD_LCD_3V3: C82.1 C139.1 C140.1 J18.4 J18.5 R176.1 R177.1 U14.1(OUT)
VDD_LCD_5V: C83.1 C84.1 C86.1 J18.1 J18.2 J18.3 U13.1(OUT)
VDD_LVDS: C100.1 C101.1 C102.1 C103.1 C142.1 C164.1 U10.35(VDD_LVDS1) U10.36(VDD_PLL) U10.38(VDD_LVDS2) U27.5(VOUT) Y2.4(VCC)
VDDIO_LVDS: C91.1 C92.1 C93.1 C94.1 C112.1 C113.1 L13.2 R73.1 U10.10(VDDIO) U10.13(VDD_RX)
GM8775C_DA0N: R89.2 U10.15(DA0N)
GM8775C_DA0P: R86.2 U10.14(DA0P)
GM8775C_DA1N: R93.2 U10.17(DA1N)
GM8775C_DA1P: R90.2 U10.16(DA1P)
GM8775C_DA2N: R97.2 U10.21(DA2N)
GM8775C_DA2P: R94.2 U10.20(DA2P)
GM8775C_DA3N: R102.2 U10.23(DA3N)
GM8775C_DA3P: R99.2 U10.22(DA3P)
GM8775C_DACN: R107.2 U10.19(DACN)
GM8775C_DACP: R104.2 U10.18(DACP)
GM8775C_RSTn: C95.1 R73.2 R187.2 U10.12(EN)
I2C1_SCL_M1: J18.9 J19.4 R74.1 ; off-sheet I2C1_SCL_M1
I2C1_SDA_M1: J18.10 J19.5 R75.1 ; off-sheet I2C1_SDA_M1
LCD_BL_PWM: R184.1 R185.1 ; off-sheet LCD_BL_PWM
LCD_CPT_INT: R81.1 R178.1 ; off-sheet LCD_CPT_INT
LCD_CPT_RST: R182.1 R183.1 ; off-sheet LCD_CPT_RST
LCD_RST: R186.1 R187.1 ; off-sheet LCD_RST
LVDS_BL_EN: R213.1 U21.3(A1) ; off-sheet LVDS_BL_EN
LVDS_BL_PWM: R185.2 R214.1 U22.3(A1)
LVDS_BLEN: J31.3 R213.2 R215.2
LVDS_BLPWM: J31.4 R214.2 R216.2
LVDS_CPT_INT: J19.3 R80.2 R178.2
LVDS_CPT_RST: J19.2 R82.2 R183.2
LVDS_TXA_CLKN: J17.15 U10.27(A_CLKN)
LVDS_TXA_CLKP: J17.16 U10.28(A_CLKP)
LVDS_TXA_D0N: J17.7 U10.33(A_Y0N)
LVDS_TXA_D0P: J17.8 U10.34(A_Y0P)
LVDS_TXA_D1N: J17.9 U10.31(A_Y1N)
LVDS_TXA_D1P: J17.10 U10.32(A_Y1P)
LVDS_TXA_D2N: J17.11 U10.29(A_Y2N)
LVDS_TXA_D2P: J17.12 U10.30(A_Y2P)
LVDS_TXA_D3N: J17.17 U10.25(A_Y3N)
LVDS_TXA_D3P: J17.18 U10.26(A_Y3P)
LVDS_TXB_CLKN: J17.27 U10.41(B_CLKN)
LVDS_TXB_CLKP: J17.28 U10.42(B_CLKP)
LVDS_TXB_D0N: J17.19 U10.47(B_Y0N)
LVDS_TXB_D0P: J17.20 U10.48(B_Y0P)
LVDS_TXB_D1N: J17.21 U10.45(B_Y1N)
LVDS_TXB_D1P: J17.22 U10.46(B_Y1P)
LVDS_TXB_D2N: J17.23 U10.43(B_Y2N)
LVDS_TXB_D2P: J17.24 U10.44(B_Y2P)
LVDS_TXB_D3N: J17.29 U10.39(B_Y3N)
LVDS_TXB_D3P: J17.30 U10.40(B_Y3P)
MIPI_BL_PWM: J18.13 R184.2
MIPI_CTP_INT: J18.11 R81.2 R176.2
MIPI_CTP_RST: J18.12 R177.2 R182.2
MIPI_DSI_CLKN: J18.24 R106.2
MIPI_DSI_CLKP: J18.23 R105.2
MIPI_DSI_D0N: J18.27 R88.2
MIPI_DSI_D0P: J18.26 R87.2
MIPI_DSI_D1N: J18.21 R92.2
MIPI_DSI_D1P: J18.20 R91.2
MIPI_DSI_D2N: J18.18 R96.2
MIPI_DSI_D2P: J18.17 R95.2
MIPI_DSI_D3N: J18.30 R101.2
MIPI_DSI_D3P: J18.29 R100.2
MIPI_DSI_TX_CLKN: R106.1 R107.1 ; off-sheet MIPI_DSI_TX_CLKN
MIPI_DSI_TX_CLKP: R104.1 R105.1 ; off-sheet MIPI_DSI_TX_CLKP
MIPI_DSI_TX_D0N: R88.1 R89.1 ; off-sheet MIPI_DSI_TX_D0N
MIPI_DSI_TX_D0P: R86.1 R87.1 ; off-sheet MIPI_DSI_TX_D0P
MIPI_DSI_TX_D1N: R92.1 R93.1 ; off-sheet MIPI_DSI_TX_D1N
MIPI_DSI_TX_D1P: R90.1 R91.1 ; off-sheet MIPI_DSI_TX_D1P
MIPI_DSI_TX_D2N: R96.1 R97.1 ; off-sheet MIPI_DSI_TX_D2N
MIPI_DSI_TX_D2P: R94.1 R95.1 ; off-sheet MIPI_DSI_TX_D2P
MIPI_DSI_TX_D3N: R101.1 R102.1 ; off-sheet MIPI_DSI_TX_D3N
MIPI_DSI_TX_D3P: R99.1 R100.1 ; off-sheet MIPI_DSI_TX_D3P
MIPI_LCD_PWR_EN: R179.1 ; off-sheet MIPI_LCD_PWR_EN
MIPI_LCD_RST: J18.15 R186.2
NetC87_1: C87.1 C88.1 C89.1 C90.1 U10.11(VCORE)
NetC138_1: C138.1 C145.1 R179.2 U13.4(EN) U14.4(EN)
NetC162_1: C162.1 U27.4(BP)
NetR74_2: R74.2 U10.1(SCL)
NetR75_2: R75.2 U10.2(SDA)
NetR76_2: R76.2 U10.8(I2C_TYPE)
NetR77_2: R77.2 U10.7(I2C_ADDR)
NetR83_1: R83.1 Y2.3(CLK)
NetR83_2: R83.2 R85.1 U10.24(REFCLK)
NetR180_1: R180.1 U13.3(ISET)
NetR181_1: R181.1 U14.3(ISET)
NetR215_1: R215.1 U21.4(B1)
NetR216_1: R216.1 U22.4(B1)

Not connected (* = marked no-connect by the designer): J18 14; U10 3(GPO_0) 4(GPO_1) 6(IRQ); Y2 1(NC)

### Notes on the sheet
- 10K
- TE
- GPIO3_B0
- 2A限流
- 3.3V
- 1.8V
- GPIO4_B6
- (near J20) VCC_LVDS电压选择(跳帽)
- GPIO3_C5
- (near R214) 3.3V IO：R213、R214接0R，U21、U22、R215、R216 NC不焊接
- 5.0V IO：R213、R214 NC不焊接，U21、U22、R215、R216焊接
- GPIO3_C6
- PWM12_M1
- GPIO3_B5
- (near R187) 注：默认LVDS触摸屏

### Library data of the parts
*#9 = TitleBlock_YHSCH: Cage Code: 1
C82 C92 C94 C101 C103 C104 C111 C112 C132 C141-C143 = CAP_NP: as C63 on sheet 07 USB3
C83 C97 C105 C113 C164 = CAP_NP: as C66 on sheet 07 USB3
C84 C110 C139 C160 = CAP_NP: as C78 on sheet 07 USB3
C86 C96 C128 C136 C138 C140 C145 = CAP_NP: as C65 on sheet 07 USB3
C87 C88 = CAP_NP: CLASS: DISCRETE; 规格: 贴片电容10nF 10% 50V X7R 0402; 规格编号: CC0402KRX7R9BB103; 条码: EBF29060245; 品牌: 国巨; 类别: 贴片电容0402; 规格书: 国巨-贴片电容.pdf; 价格: 0.003808; 生命周期: 量产
C89 C90 = CAP_NP: CLASS: DISCRETE; 生命周期: 量产; 价格: 0.01191; 规格书: 风华电容.pdf; 类别: 贴片电容0402; 品牌: 风华; 条码: EBF29060121; 规格编号: 0402X105K100NT; 规格: 贴片电容1uF 10% 10V X5R 0402
C91 C93 C100 C102 = CAP_NP: CLASS: DISCRETE; 生命周期: 量产; 价格: 0.003808; 规格书: 国巨-贴片电容.pdf; 类别: 贴片电容0402; 品牌: 国巨; 条码: EBF29060245; 规格编号: CC0402KRX7R9BB103; 规格: 贴片电容10nF 10% 50V X7R 0402
C95 = CAP_NP: CLASS: DISCRETE; 规格: 贴片电容0.22uF 20% 50V X5R 0402; 规格编号: UMK105BJ224MV-F; 条码: EBF29060266; 品牌: 太诱; 类别: 贴片电容0402; 规格书: 太诱-贴片电容.pdf; 价格: 0.074942; 生命周期: 量产
C98 = CAP_NP: as C157-C159 on sheet 08 LED_IR_GPIO引出_MASKRO
C99 = CAP_NP: CLASS: DISCRETE; 规格: 贴片电容22uF 20% 25V X5R 0805; 规格编号: 0805X226M250NT; 条码: EBF29060173; 品牌: 风华; 类别: 贴片电容0805; 规格书: 风华电容.pdf; 价格: 0.285631; 生命周期: 量产
C162 = CAP_NP: CLASS: DISCRETE; 生命周期: 量产; 价格: 0.009905; 规格书: 风华电容.pdf; 类别: 贴片电容0402; 品牌: 风华; 条码: EBF29060246; 规格编号: 0402B223K500NT; 规格: 贴片电容22nF 10% 50V X7R 0402
J17 = 2X15PIN: 备注: RK3566广告机; 规格书: 华灿天禄_2mm_弯插排针.pdf; 品牌: 华灿天禄; 规格编号: PZ200-2-15-W; 规格: 弯插双排排针 总PIN数30 间距2.0mm; 条码: EBFCIS230518163241; 类别: 2.00mm弯插双排排针; 生命周期: 量产
J18 = FPC-30P: 规格: FPC连接器 针脚数30 间距0.5mm 高度2.0mm 下接 卧贴 翻盖式; 规格编号: FPC-05F-30PH20; 条码: EBF29040079; 品牌: 讯普; 类别: FPC连接器; 规格书: FPC-05F-NPH20.pdf; 生命周期: 量产
J19 J31 = 1X6PIN_SH: 规格: 间距：2mm 插针结构：1x6P 排数：1 每排PIN数：6 公母：公型插针 安装方式：卧贴 额定电流：2A 工作温度范围：-25℃~+85℃; 条码: EBFCIS230215171117; 品牌: 博穆精密; 类别: PH连接器; 规格书: 博穆精密_PH2.0-A.pdf; 价格: 0.47; 生命周期: 量产
J20 = 2X3PIN: 规格: 直插双排排针 总PIN数6 间距2.0mm; 条码: EBFCIS230522093235; 类别: 2.00mm直插双排排针; 规格书: 长江连接器_2MM直插双排排针.pdf; 生命周期: 量产; 规格编号: A2005WV-2x3P; 品牌: 长江连接器; 备注: RK3566广告机
L13 = BEAD: as L10 on sheet 07 USB3
R73 = RES: CLASS: DISCRETE; 规格: 贴片电阻4.7K 1% 1/16W 0402; 规格编号: RI0402L4701FT; 条码: EBF29070047; 品牌: 合科泰; 类别: 贴片电阻0402; 规格书: 合科泰-RI系列电阻.pdf; 生命周期: 量产
R74 R75 = RES: as R238 on sheet 08 LED_IR_GPIO引出_MASKRO
R76 R77 R80 R82 = RES: as R188 on sheet 08 LED_IR_GPIO引出_MASKRO
R78 R84 = RES: CLASS: DISCRETE; 生命周期: 量产; 规格书: 合科泰-RI系列电阻.pdf; 类别: 贴片电阻0603; 品牌: 合科泰; 条码: EBF29070063; 规格编号: RI0603L0000FT; 规格: 贴片电阻0R 1% 1/10W 0603
R79 = RES: CLASS: DISCRETE; 规格: 贴片电阻0R 1% 1/10W 0603; 规格编号: RI0603L0000FT; 条码: EBF29070063; 品牌: 合科泰; 类别: 贴片电阻0603; 规格书: 合科泰-RI系列电阻.pdf; 生命周期: 量产
R81 R83 R176 R177 R182 R184 R186 R213 R214 = RES: as R259 on sheet 08 LED_IR_GPIO引出_MASKRO
R85 R178 R183 R185 R187 = RES: as R244 on sheet 08 LED_IR_GPIO引出_MASKRO
R86 R89 R90 R93 R94 R97 R99 R102 R104 R107 = RES: CLASS: DISCRETE; 生命周期: 量产; 规格书: 合科泰-RI系列电阻.pdf; 类别: 贴片电阻0201; 品牌: 合科泰; 条码: EBF29070164; 规格编号: RI0201L0000FT; 规格: 贴片电阻0R 1% 1/20W 0201
R87 R88 R91 R92 R95 R96 R100 R101 R105 R106 = RES: CLASS: DISCRETE; 规格: 贴片电阻NC 预留; 条码: EBF29070002; 类别: 贴片电阻0201; 生命周期: 量产
R179 = RES: as R56 on sheet 07 USB3
R180 R181 = RES: as R57 on sheet 07 USB3
R215 R216 = RES: as R58 on sheet 07 USB3
U10 = GM8775C: 备注: RK3566广告机; 生命周期: 量产; 规格书: 振芯_GM8775C_MIPI转单双通道LVDS.pdf; 类别: 视频音频接口芯片; 品牌: 振芯; 条码: EBFCIS230518165741; 规格: DSI转双通道LVDS发送器 最大支持4Gbps速率 LVDS时钟高达154MHz 支持视频格式 FULL HD(1920 x 1200)
U13 U14 = MT9700: as U9 on sheet 07 USB3
U21 U22 = 74LVC1T45: 规格: 转换器、电平移位器通道类型：双向 VCCA、VCCB：1.65V~5.5V 输出类型：三态、非反相; 条码: EBF29340002; 品牌: 美台; 类别: 电平转换器; 规格书: 美台_74LVC1T45FZ4-7.pdf; 价格: 0.6093; 生命周期: 量产
U27 = RT9193-XXGB: 可替代料: EBF29110001; 丝印: DC=XX; 生命周期: 量产; 价格: 0.7268; 规格书: RT9193-GB.pdf; 类别: 电源管理-LDO; 品牌: 台湾立锜; 规格: 低压差LDO 输入2.5V-5.5V 输出1.8V 最大电流300mA 压差220mV@300mA 静态电流0.01μA
Y2 = Oscillator_4P: 类别: 贴片晶振 3225

## Sheet 10 MIPI CSI接口.SchDoc
size 297 x 209 mm
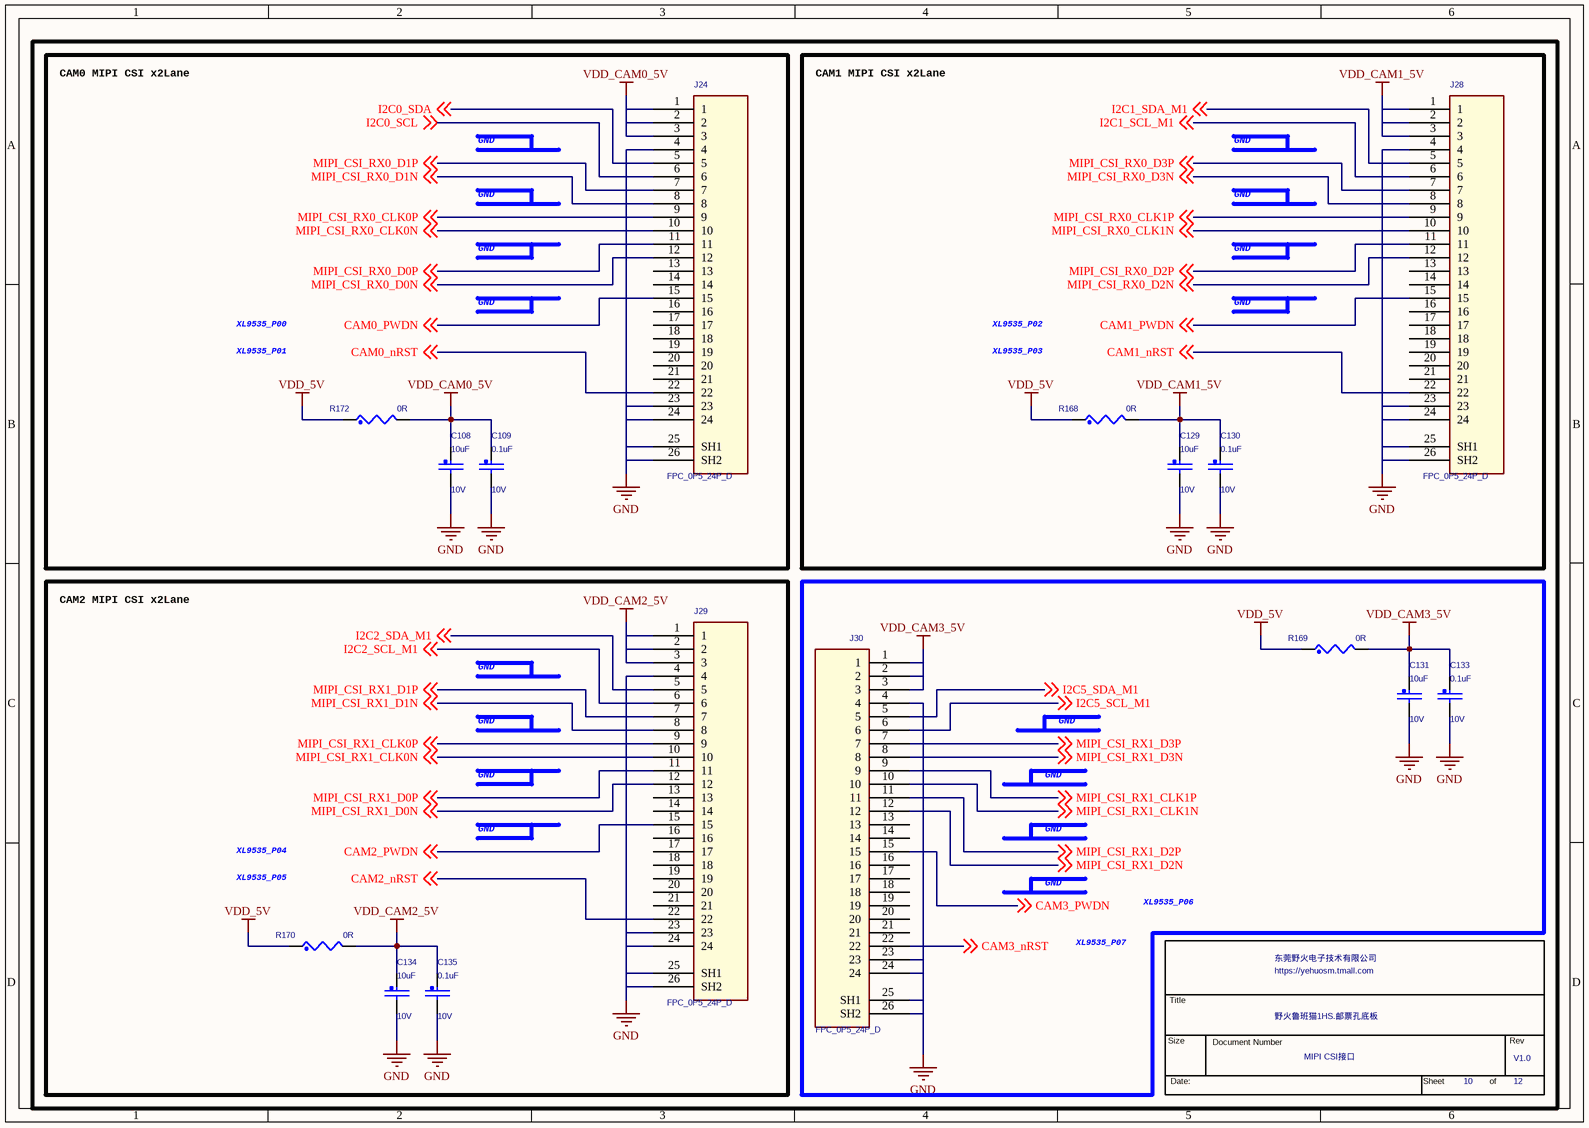
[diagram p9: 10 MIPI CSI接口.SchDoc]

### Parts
(Parts that share a designator on the sheet are numbered #1, #2 ... from top to bottom, then left to right.)
*#10  Page Count: 12  Page Number: 10  OrgName: 东莞野火电子技术有限公司  Title: 野火鲁班猫1HS.邮票孔底板  RevCode: V1.0  Doc: MIPI CSI接口  (hidden comment: TitleBlock_YHSCH)  (graphical)
C108  10uF  Voltage: 10V  [C0402]
C109  0.1uF  Voltage: 10V  [C0402]
C129  10uF  Voltage: 10V  [C0402]
C130  0.1uF  Voltage: 10V  [C0402]
C131  10uF  Voltage: 10V  [C0402]
C133  0.1uF  Voltage: 10V  [C0402]
C134  10uF  Voltage: 10V  [C0402]
C135  0.1uF  Voltage: 10V  [C0402]
J24  FPC_0P5_24P_D  [fpc_24p_0p5]
J28  FPC_0P5_24P_D  [fpc_24p_0p5]
J29  FPC_0P5_24P_D  [fpc_24p_0p5]
J30  FPC_0P5_24P_D  [fpc_24p_0p5]
R168  0R  [R0402]
R169  0R  [R0402]
R170  0R  [R0402]
R172  0R  [R0402]

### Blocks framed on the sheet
CAM0 MIPI CSI x2Lane: C108 C109 J24 R172
CAM1 MIPI CSI x2Lane: C129 C130 J28 R168
CAM2 MIPI CSI x2Lane: C134 C135 J29 R170

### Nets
GND: C108.2 C109.2 C129.2 C130.2 C131.2 C133.2 C134.2 C135.2 J24.4 J24.23 J24.24 J24.25(SH1) J24.26(SH2) J28.4 J28.23 J28.24 J28.25(SH1) J28.26(SH2) J29.4 J29.23 J29.24 J29.25(SH1) J29.26(SH2) J30.4 J30.23 J30.24 J30.25(SH1) J30.26(SH2)
VDD_5V: R168.1 R169.1 R170.1 R172.1
VDD_CAM0_5V: C108.1 C109.1 J24.1 J24.2 J24.3 R172.2
VDD_CAM1_5V: C129.1 C130.1 J28.1 J28.2 J28.3 R168.2
VDD_CAM2_5V: C134.1 C135.1 J29.1 J29.2 J29.3 R170.2
VDD_CAM3_5V: C131.1 C133.1 J30.1 J30.2 J30.3 R169.2
CAM0_nRST: J24.22 ; off-sheet CAM0_nRST
CAM0_PWDN: J24.15 ; off-sheet CAM0_PWDN
CAM1_nRST: J28.22 ; off-sheet CAM1_nRST
CAM1_PWDN: J28.15 ; off-sheet CAM1_PWDN
CAM2_nRST: J29.22 ; off-sheet CAM2_nRST
CAM2_PWDN: J29.15 ; off-sheet CAM2_PWDN
CAM3_nRST: J30.22 ; off-sheet CAM3_nRST
CAM3_PWDN: J30.15 ; off-sheet CAM3_PWDN
I2C0_SCL: J24.6 ; off-sheet I2C0_SCL
I2C0_SDA: J24.5 ; off-sheet I2C0_SDA
I2C1_SCL_M1: J28.6 ; off-sheet I2C1_SCL_M1
I2C1_SDA_M1: J28.5 ; off-sheet I2C1_SDA_M1
I2C2_SCL_M1: J29.6 ; off-sheet I2C2_SCL_M1
I2C2_SDA_M1: J29.5 ; off-sheet I2C2_SDA_M1
I2C5_SCL_M1: J30.6 ; off-sheet I2C5_SCL_M1
I2C5_SDA_M1: J30.5 ; off-sheet I2C5_SDA_M1
MIPI_CSI_RX0_CLK0N: J24.10 ; off-sheet MIPI_CSI_RX0_CLK0N
MIPI_CSI_RX0_CLK0P: J24.9 ; off-sheet MIPI_CSI_RX0_CLK0P
MIPI_CSI_RX0_CLK1N: J28.10 ; off-sheet MIPI_CSI_RX0_CLK1N
MIPI_CSI_RX0_CLK1P: J28.9 ; off-sheet MIPI_CSI_RX0_CLK1P
MIPI_CSI_RX0_D0N: J24.12 ; off-sheet MIPI_CSI_RX0_D0N
MIPI_CSI_RX0_D0P: J24.11 ; off-sheet MIPI_CSI_RX0_D0P
MIPI_CSI_RX0_D1N: J24.8 ; off-sheet MIPI_CSI_RX0_D1N
MIPI_CSI_RX0_D1P: J24.7 ; off-sheet MIPI_CSI_RX0_D1P
MIPI_CSI_RX0_D2N: J28.12 ; off-sheet MIPI_CSI_RX0_D2N
MIPI_CSI_RX0_D2P: J28.11 ; off-sheet MIPI_CSI_RX0_D2P
MIPI_CSI_RX0_D3N: J28.8 ; off-sheet MIPI_CSI_RX0_D3N
MIPI_CSI_RX0_D3P: J28.7 ; off-sheet MIPI_CSI_RX0_D3P
MIPI_CSI_RX1_CLK0N: J29.10 ; off-sheet MIPI_CSI_RX1_CLK0N
MIPI_CSI_RX1_CLK0P: J29.9 ; off-sheet MIPI_CSI_RX1_CLK0P
MIPI_CSI_RX1_CLK1N: J30.10 ; off-sheet MIPI_CSI_RX1_CLK1N
MIPI_CSI_RX1_CLK1P: J30.9 ; off-sheet MIPI_CSI_RX1_CLK1P
MIPI_CSI_RX1_D0N: J29.12 ; off-sheet MIPI_CSI_RX1_D0N
MIPI_CSI_RX1_D0P: J29.11 ; off-sheet MIPI_CSI_RX1_D0P
MIPI_CSI_RX1_D1N: J29.8 ; off-sheet MIPI_CSI_RX1_D1N
MIPI_CSI_RX1_D1P: J29.7 ; off-sheet MIPI_CSI_RX1_D1P
MIPI_CSI_RX1_D2N: J30.12 ; off-sheet MIPI_CSI_RX1_D2N
MIPI_CSI_RX1_D2P: J30.11 ; off-sheet MIPI_CSI_RX1_D2P
MIPI_CSI_RX1_D3N: J30.8 ; off-sheet MIPI_CSI_RX1_D3N
MIPI_CSI_RX1_D3P: J30.7 ; off-sheet MIPI_CSI_RX1_D3P

Not connected (* = marked no-connect by the designer): J24 13 14 16 17 18 19 20 21; J28 13 14 16 17 18 19 20 21; J29 13 14 16 17 18 19 20 21; J30 13 14 16 17 18 19 20 21

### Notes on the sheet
- GND
- XL9535_P00
- XL9535_P02
- XL9535_P01
- XL9535_P03
- XL9535_P04
- XL9535_P05
- (near *#10) XL9535_P07
- (near *#10) XL9535_P06

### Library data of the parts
*#10 = TitleBlock_YHSCH: Cage Code: 1
C108 = CAP_NP: as C78 on sheet 07 USB3
C109 C130 C133 C135 = CAP_NP: as C65 on sheet 07 USB3
C129 C131 C134 = CAP_NP: as C66 on sheet 07 USB3
J24 J28 J29 = FPC-24P: 可替代料: EBF29040059; 生命周期: 量产; 价格: 0.368739; 规格书: 钜硕电子-FPC间距0.5mm.pdf; 类别: FPC连接器; 品牌: 钜硕电子; 规格编号: AFC01-S24FCA-00; 规格: FPC连接器 针脚数24 间距0.5mmm 下接 卧贴 翻盖式
J30 = FPC-24P: 规格: FPC连接器 针脚数24 间距0.5mmm 下接 卧贴 翻盖式; 规格编号: AFC01-S24FCA-00; 条码: EBF29040059; 品牌: 钜硕电子; 类别: FPC连接器; 规格书: 钜硕电子-FPC间距0.5mm.pdf; 价格: 0.368739; 生命周期: 量产
R168-R170 = RES: as R54 on sheet 07 USB3
R172 = RES: as R244 on sheet 08 LED_IR_GPIO引出_MASKRO

## Sheet 11 WIFI_蓝牙.SchDoc
size 297 x 209 mm
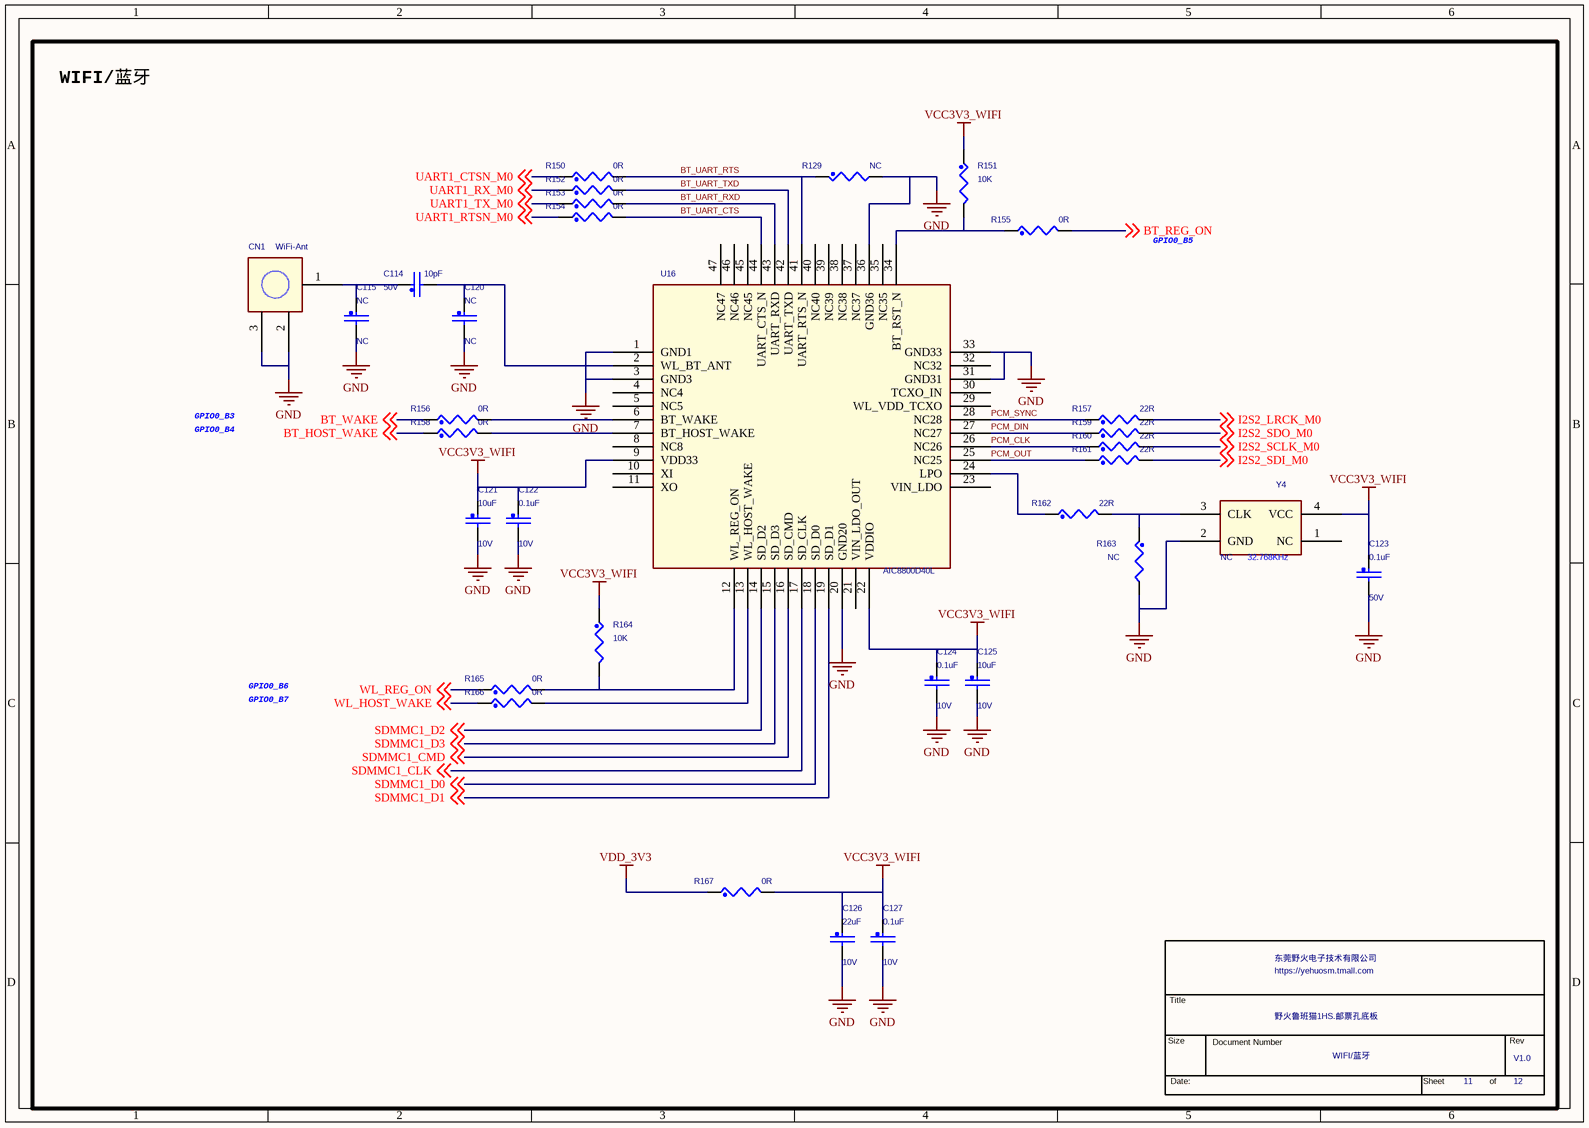
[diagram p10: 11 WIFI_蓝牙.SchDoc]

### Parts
(Parts that share a designator on the sheet are numbered #1, #2 ... from top to bottom, then left to right.)
*#11  Page Count: 12  Page Number: 11  OrgName: 东莞野火电子技术有限公司  Title: 野火鲁班猫1HS.邮票孔底板  RevCode: V1.0  Doc: WIFI/蓝牙  (hidden comment: TitleBlock_YHSCH)  (graphical)
C114  10pF  Voltage: 50V  [C0402]
C115  NC  [C0402]
C120  NC  [C0402]
C121  10uF  Voltage: 10V  [C0402]
C122  0.1uF  Voltage: 10V  [C0402]
C123  0.1uF  Voltage: 50V  [C0402]
C124  0.1uF  Voltage: 10V  [C0402]
C125  10uF  Voltage: 10V  [C0402]
C126  22uF  Voltage: 10V  [C0603]
C127  0.1uF  Voltage: 10V  [C0402]
CN1  WiFi-Ant  [UFL-3]
R129  NC  [R0402]
R150  0R  [R0402]
R151  10K  [R0402]
R152  0R  [R0402]
R153  0R  [R0402]
R154  0R  [R0402]
R155  0R  [R0402]
R156  0R  [R0402]
R157  22R  [R0402]
R158  0R  [R0402]
R159  22R  [R0402]
R160  22R  [R0402]
R161  22R  [R0402]
R162  22R  [R0402]
R163  NC  [R0402]
R164  10K  [R0402]
R165  0R  [R0402]
R166  0R  [R0402]
R167  0R  [R0603]
U16  AIC8800D40L  [AP6212]
Y4  NC  [3225]

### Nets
GND: C115.2 C120.2 C121.2 C122.2 C123.2 C124.2 C125.2 C126.2 C127.2 CN1.2 CN1.3 R129.2 R163.2 U16.1(GND1) U16.3(GND3) U16.20(GND20) U16.31(GND31) U16.33(GND33) U16.36(GND36) Y4.2(GND)
VCC3V3_WIFI: C121.1 C122.1 C123.1 C124.1 C125.1 C126.1 C127.1 R151.1 R164.1 R167.2 U16.9(VDD33) U16.22(VDDIO) Y4.4(VCC)
VDD_3V3: R167.1
BT_HOST_WAKE: R158.1 ; off-sheet BT_HOST_WAKE
BT_REG_ON: R155.2 ; off-sheet BT_REG_ON
BT_UART_CTS: R154.2 U16.44(UART_CTS_N)
BT_UART_RTS: R129.1 R150.2 U16.41(UART_RTS_N)
BT_UART_RXD: R153.2 U16.43(UART_RXD)
BT_UART_TXD: R152.2 U16.42(UART_TXD)
BT_WAKE: R156.1 ; off-sheet BT_WAKE
I2S2_LRCK_M0: R157.2 ; off-sheet I2S2_LRCK_M0
I2S2_SCLK_M0: R160.2 ; off-sheet I2S2_SCLK_M0
I2S2_SDI_M0: R161.2 ; off-sheet I2S2_SDI_M0
I2S2_SDO_M0: R159.2 ; off-sheet I2S2_SDO_M0
PCM_CLK: R160.1 U16.26(NC26)
PCM_DIN: R159.1 U16.27(NC27)
PCM_OUT: R161.1 U16.25(NC25)
PCM_SYNC: R157.1 U16.28(NC28)
SDMMC1_CLK: U16.17(SD_CLK) ; off-sheet SDMMC1_CLK
SDMMC1_CMD: U16.16(SD_CMD) ; off-sheet SDMMC1_CMD
SDMMC1_D0: U16.18(SD_D0) ; off-sheet SDMMC1_D0
SDMMC1_D1: U16.19(SD_D1) ; off-sheet SDMMC1_D1
SDMMC1_D2: U16.14(SD_D2) ; off-sheet SDMMC1_D2
SDMMC1_D3: U16.15(SD_D3) ; off-sheet SDMMC1_D3
UART1_CTSN_M0: R150.1 ; off-sheet UART1_CTSN_M0
UART1_RTSN_M0: R154.1 ; off-sheet UART1_RTSN_M0
UART1_RX_M0: R152.1 ; off-sheet UART1_RX_M0
UART1_TX_M0: R153.1 ; off-sheet UART1_TX_M0
WL_HOST_WAKE: R166.1 ; off-sheet WL_HOST_WAKE
WL_REG_ON: R165.1 ; off-sheet WL_REG_ON
NetC114_1: C114.1 C115.1 CN1.1
NetC114_2: C114.2 C120.1 U16.2(WL_BT_ANT)
NetR151_2: R151.2 R155.1 U16.34(BT_RST_N)
NetR156_2: R156.2 U16.6(BT_WAKE)
NetR158_2: R158.2 U16.7(BT_HOST_WAKE)
NetR162_1: R162.1 U16.24(LPO)
NetR162_2: R162.2 R163.1 Y4.3(CLK)
NetR164_2: R164.2 R165.2 U16.12(WL_REG_ON)
NetR166_2: R166.2 U16.13(WL_HOST_WAKE)

Not connected (* = marked no-connect by the designer): U16 4(NC4) 5(NC5) 8(NC8) 10(XI) 11(XO) 21(VIN_LDO_OUT) 23(VIN_LDO) 29(WL_VDD_TCXO) 30(TCXO_IN) 32(NC32) 35(NC35) 37(NC37) 38(NC38) 39(NC39) 40(NC40) 45(NC45) 46(NC46) 47(NC47); Y4 1(NC)

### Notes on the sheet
- WIFI/蓝牙
- GPIO0_B5
- GPIO0_B4
- GPIO0_B3
- (near Y4) 32.768KHz
- GPIO0_B6
- GPIO0_B7

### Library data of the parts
*#11 = TitleBlock_YHSCH: Cage Code: 1
C114 = CAP_NP: CLASS: DISCRETE; 规格: 贴片电容10pF 5% 50V C0G 0402; 规格编号: 0402CG100J500NT; 条码: EBF29060127; 品牌: 风华; 类别: 贴片电容0402; 规格书: 风华电容.pdf; 价格: 0.00453; 生命周期: 量产
C115 C120 = CAP_NP: as C74 on sheet 07 USB3
C121 C125 = CAP_NP: as C78 on sheet 07 USB3
C122 C124 C127 = CAP_NP: as C65 on sheet 07 USB3
C123 = CAP_NP: CLASS: DISCRETE; 生命周期: 量产; 价格: 0.029826; 规格书: 风华电容.pdf; 类别: 贴片电容0402; 品牌: 风华; 条码: EBF29060118; 规格编号: 0402X104K500NT; 规格: 贴片电容0.1uF 10% 50V X5R 0402
C126 = CAP_NP: CLASS: DISCRETE; 生命周期: 量产; 价格: 0.078818; 规格书: 三星电容.pdf; 类别: 贴片电容0603; 品牌: 三星; 条码: EBF29060163; 规格编号: CL10A226MP8NUNE; 规格: 贴片电容22uF 20% 10V X5R 0603
CN1 = WIFI_ANT: 规格: RF同轴连接器（天线座）; 规格编号: KH-IPEX-K501-29; 条码: EBF430005; 品牌: 金航标; 类别: WiFi天线座; 规格书: 金航标-天线座.pdf; 价格: 0.247224; 生命周期: 量产
R129 = RES: as R259 on sheet 08 LED_IR_GPIO引出_MASKRO
R150 R152 R153 R156 R158 = RES: as R244 on sheet 08 LED_IR_GPIO引出_MASKRO
R151 R164 = RES: as R58 on sheet 07 USB3
R154 R155 R165 R166 = RES: as R54 on sheet 07 USB3
R157 R159-R162 = RES: as R261 on sheet 08 LED_IR_GPIO引出_MASKRO
R163 = RES: as R238 on sheet 08 LED_IR_GPIO引出_MASKRO
R167 = RES: as R79 on sheet 09 MIPI DSI_LVDS接口
U16 = AP6212: 规格: AIC8800D40L wifi模块 工作电压3.3V IO电压3.3V/1.8V SDIO接口 无线数据速率286Mbps 无线标准IEEE802.11a/b/g/n/ac/ax; 规格编号: BL-M8189FS6; 条码: EBFCIS241205104349; 品牌: 启芯时代; 类别: WiFi模组; 规格书: 启芯时代_Mstlink-20800D4-L0_SPEC_20230523_V1.0.pdf; 生命周期: 量产; 备注: 广告机
Y4 = Oscillator_4P: 类别: 贴片晶振 3225

## Sheet 12 UART_RS232_RS485.SchDoc
size 297 x 209 mm
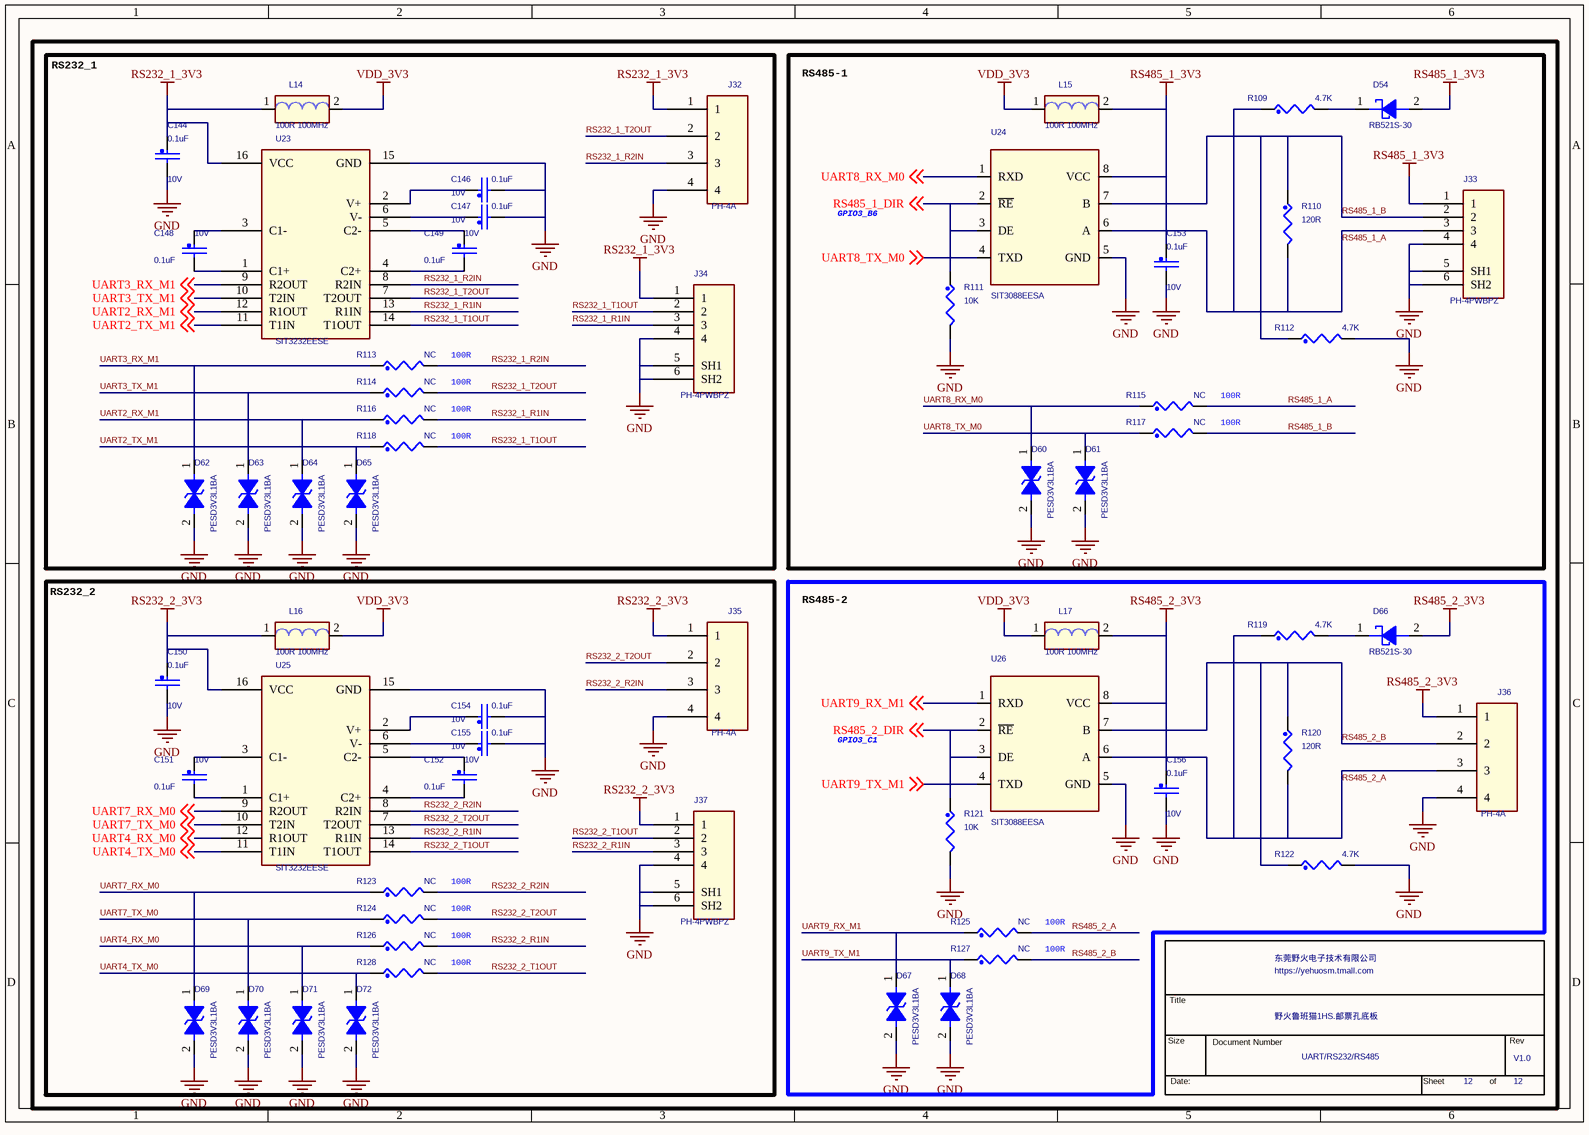
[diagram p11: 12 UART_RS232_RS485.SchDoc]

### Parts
(Parts that share a designator on the sheet are numbered #1, #2 ... from top to bottom, then left to right.)
*#12  Page Count: 12  OrgName: 东莞野火电子技术有限公司  Title: 野火鲁班猫1HS.邮票孔底板  RevCode: V1.0  Doc: UART/RS232/RS485  (hidden comment: TitleBlock_YHSCH)  (graphical)
C144  0.1uF  Voltage: 10V  [C0402]
C146  0.1uF  Voltage: 10V  [C0402]
C147  0.1uF  Voltage: 10V  [C0402]
C148  0.1uF  Voltage: 10V  [C0402]
C149  0.1uF  Voltage: 10V  [C0402]
C150  0.1uF  Voltage: 10V  [C0402]
C151  0.1uF  Voltage: 10V  [C0402]
C152  0.1uF  Voltage: 10V  [C0402]
C153  0.1uF  Voltage: 10V  [C0402]
C154  0.1uF  Voltage: 10V  [C0402]
C155  0.1uF  Voltage: 10V  [C0402]
C156  0.1uF  Voltage: 10V  [C0402]
D54  RB521S-30  [SOD523]
D60  PESD3V3L1BA  [D0603/SMD]
D61  PESD3V3L1BA  [D0603/SMD]
D62  PESD3V3L1BA  [D0603/SMD]
D63  PESD3V3L1BA  [D0603/SMD]
D64  PESD3V3L1BA  [D0603/SMD]
D65  PESD3V3L1BA  [D0603/SMD]
D66  RB521S-30  [SOD523]
D67  PESD3V3L1BA  [D0603/SMD]
D68  PESD3V3L1BA  [D0603/SMD]
D69  PESD3V3L1BA  [D0603/SMD]
D70  PESD3V3L1BA  [D0603/SMD]
D71  PESD3V3L1BA  [D0603/SMD]
D72  PESD3V3L1BA  [D0603/SMD]
J32  PH-4A  [PH-1X4-2P0]
J33  PH-4PWBPZ  [ph2r0-a-1x4]
J34  PH-4PWBPZ  [ph2r0-a-1x4]
J35  PH-4A  [PH-1X4-2P0]
J36  PH-4A  [PH-1X4-2P0]
J37  PH-4PWBPZ  [ph2r0-a-1x4]
L14  100R 100MHz  [L0603]
L15  100R 100MHz  [L0603]
L16  100R 100MHz  [L0603]
L17  100R 100MHz  [L0603]
R109  4.7K  [R0402]
R110  120R  [R0402]
R111  10K  [R0603]
R112  4.7K  [R0402]
R113  NC  [R0402]
R114  NC  [R0402]
R115  NC  [R0402]
R116  NC  [R0402]
R117  NC  [R0402]
R118  NC  [R0402]
R119  4.7K  [R0402]
R120  120R  [R0402]
R121  10K  [R0603]
R122  4.7K  [R0402]
R123  NC  [R0402]
R124  NC  [R0402]
R125  NC  [R0402]
R126  NC  [R0402]
R127  NC  [R0402]
R128  NC  [R0402]
U23  SIT3232EESE  [16]
U24  SIT3088EESA  [SOP8]
U25  SIT3232EESE  [16]
U26  SIT3088EESA  [SOP8]

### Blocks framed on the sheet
RS232_1: C144 C146-C149 D62-D65 J32 J34 L14 R113 R114 R116 R118 U23
RS485-1: C153 D54 D60 D61 J33 L15 R109-R112 R115 R117 U24
RS232_2: C150-C152 C154 C155 D69-D72 J35 J37 L16 R123 R124 R126 R128 U25
RS485-2: C156 D66-D68 J36 L17 R119-R122 R125 R127 U26

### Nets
GND: C144.2 C146.2 C147.2 C150.2 C153.2 C154.2 C155.2 C156.2 D60.2 D61.2 D62.2 D63.2 D64.2 D65.2 D67.2 D68.2 D69.2 D70.2 D71.2 D72.2 J32.4 J33.4 J33.5(SH1) J33.6(SH2) J34.4 J34.5(SH1) J34.6(SH2) J35.4 J36.4 J37.4 J37.5(SH1) J37.6(SH2) R111.2 R112.2 R121.2 R122.2 U23.15(GND) U24.5(GND) U25.15(GND) U26.5(GND)
RS232_1_3V3: C144.1 J32.1 J34.1 L14.1 U23.16(VCC)
RS232_2_3V3: C150.1 J35.1 J37.1 L16.1 U25.16(VCC)
RS485_1_3V3: C153.1 D54.2 J33.1 L15.2 U24.8(VCC)
RS485_2_3V3: C156.1 D66.2 J36.1 L17.2 U26.8(VCC)
VDD_3V3: L14.2 L15.1 L16.2 L17.1
RS232_1_R1IN: J34.3 R116.2 U23.13(R1IN)
RS232_1_R2IN: J32.3 R113.2 U23.8(R2IN)
RS232_1_T1OUT: J34.2 R118.2 U23.14(T1OUT)
RS232_1_T2OUT: J32.2 R114.2 U23.7(T2OUT)
RS232_2_R1IN: J37.3 R126.2 U25.13(R1IN)
RS232_2_R2IN: J35.3 R123.2 U25.8(R2IN)
RS232_2_T1OUT: J37.2 R128.2 U25.14(T1OUT)
RS232_2_T2OUT: J35.2 R124.2 U25.7(T2OUT)
RS485_1_A: J33.3 R109.1 R110.2 R115.2 U24.6(A)
RS485_1_B: J33.2 R110.1 R112.1 R117.2 U24.7(B)
RS485_1_DIR: R111.1 U24.2(~{RE}) U24.3(DE) ; off-sheet RS485_1_DIR
RS485_2_A: J36.3 R119.1 R120.2 R125.2 U26.6(A)
RS485_2_B: J36.2 R120.1 R122.1 R127.2 U26.7(B)
RS485_2_DIR: R121.1 U26.2(~{RE}) U26.3(DE) ; off-sheet RS485_2_DIR
UART2_RX_M1: D64.1 R116.1 U23.12(R1OUT) ; off-sheet UART2_RX_M1
UART2_TX_M1: D65.1 R118.1 U23.11(T1IN) ; off-sheet UART2_TX_M1
UART3_RX_M1: D62.1 R113.1 U23.9(R2OUT) ; off-sheet UART3_RX_M1
UART3_TX_M1: D63.1 R114.1 U23.10(T2IN) ; off-sheet UART3_TX_M1
UART4_RX_M0: D71.1 R126.1 U25.12(R1OUT) ; off-sheet UART4_RX_M0
UART4_TX_M0: D72.1 R128.1 U25.11(T1IN) ; off-sheet UART4_TX_M0
UART7_RX_M0: D69.1 R123.1 U25.9(R2OUT) ; off-sheet UART7_RX_M0
UART7_TX_M0: D70.1 R124.1 U25.10(T2IN) ; off-sheet UART7_TX_M0
UART8_RX_M0: D60.1 R115.1 U24.1(RXD) ; off-sheet UART8_RX_M0
UART8_TX_M0: D61.1 R117.1 U24.4(TXD) ; off-sheet UART8_TX_M0
UART9_RX_M1: D67.1 R125.1 U26.1(RXD) ; off-sheet UART9_RX_M1
UART9_TX_M1: D68.1 R127.1 U26.4(TXD) ; off-sheet UART9_TX_M1
NetC146_1: C146.1 U23.2(V+)
NetC147_1: C147.1 U23.6(V-)
NetC148_1: C148.1 U23.3(C1-)
NetC148_2: C148.2 U23.1(C1+)
NetC149_1: C149.1 U23.5(C2-)
NetC149_2: C149.2 U23.4(C2+)
NetC151_1: C151.1 U25.3(C1-)
NetC151_2: C151.2 U25.1(C1+)
NetC152_1: C152.1 U25.5(C2-)
NetC152_2: C152.2 U25.4(C2+)
NetC154_1: C154.1 U25.2(V+)
NetC155_1: C155.1 U25.6(V-)
NetD54_1: D54.1 R109.2
NetD66_1: D66.1 R119.2

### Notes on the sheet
- GPIO3_B6
- 100R
- GPIO3_C1

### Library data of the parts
*#12 = TitleBlock_YHSCH: Cage Code: 1
C144 C146-C156 = CAP_NP: as C63 on sheet 07 USB3
D54 D66 = DIODE_SCHTKY: CLASS: IC; 规格: 直流反向耐压(Vr)：30V 平均整流电流(Io)：200mA 正向压降(Vf)：500mV@200mA 30V@100mA,VF=350mV@10mA; 条码: EBFCIS221114153437; 品牌: 江苏长电; 类别: 贴片肖特基二极管; 规格书: 江苏长电_RB521S-30.pdf; 价格: 0.06781; 生命周期: 量产
D60 D61 = DIODE BI-DIR TRIG: as D23 on sheet 07 USB3
D62-D65 D67-D72 = DIODE BI-DIR TRIG: as D30 on sheet 07 USB3
J32 J35 J36 = 1X4PIN: 规格: 直针PH2.0-4P 间距2.0MM 拔插式 接插件; 条码: EBF29020025; 品牌: 博穆精密; 类别: PH连接器; 规格书: 博穆精密-PH2.0.pdf; 价格: 0.017; 生命周期: 量产
J33 J34 J37 = 1X4PIN_SH: as J38 on sheet 07 USB3
L14-L16 = BEAD: as L10 on sheet 07 USB3
L17 = BEAD: as L11 on sheet 07 USB3
R109 R112 = RES: CLASS: DISCRETE; 生命周期: 量产; 规格书: 合科泰-RI系列电阻.pdf; 类别: 贴片电阻0402; 品牌: 合科泰; 条码: EBF29070047; 规格编号: RI0402L4701FT; 规格: 贴片电阻4.7K 1% 1/16W 0402
R110 = RES: CLASS: DISCRETE; 生命周期: 量产; 规格书: 厚声-无铅厚膜电阻.pdf; 类别: 贴片电阻0402; 品牌: 厚声; 条码: EBF29070275; 规格编号: 0402WGF1200TCE; 规格: 贴片电阻120R 1% 1/16W 0402; 价格: 0.002198
R111 = RES: CLASS: DISCRETE; 规格: 贴片电阻10K 1% 1/10W 0603; 规格编号: RI0603L1002FT; 条码: EBF29070074; 品牌: 合科泰; 类别: 贴片电阻0603; 规格书: 合科泰-RI系列电阻.pdf; 生命周期: 量产
R113 R114 R123 R124 = RES: as R238 on sheet 08 LED_IR_GPIO引出_MASKRO
R115-R118 R125-R128 = RES: as R259 on sheet 08 LED_IR_GPIO引出_MASKRO
R119 R122 = RES: as R73 on sheet 09 MIPI DSI_LVDS接口
R120 = RES: as R237 on sheet 08 LED_IR_GPIO引出_MASKRO
R121 = RES: CLASS: DISCRETE; 生命周期: 量产; 规格书: 合科泰-RI系列电阻.pdf; 类别: 贴片电阻0603; 品牌: 合科泰; 条码: EBF29070074; 规格编号: RI0603L1002FT; 规格: 贴片电阻10K 1% 1/10W 0603
U23 U25 = MAX3232CSE: 备注: 鲁班猫; 规格: RS232芯片 收发器 驱动器/接收器数：2/2 协议类别RS232 电源电压3.0V~5.5V 数据速率96kbps; 条码: EBFCIS231207155139; 品牌: 芯力特; 类别: RS232芯片; 规格书: 芯力特_SIT3232E-V1.17-cn.pdf; 生命周期: 量产
U24 U26 = SIT3088E-8P: CLASS: IC; 备注: 鲁班猫; 生命周期: 量产; 规格书: 芯力特_SIT3088E-V1.8_cn.pdf; 类别: RS485/RS422芯片; 品牌: 芯力特; 条码: EBFCIS231207153322; 规格: RS-485/RS-422芯片 收发器 允许256个器件连接总线 协议类别RS-485 电源电压3.0V~5.5V 数据速率14Mbps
